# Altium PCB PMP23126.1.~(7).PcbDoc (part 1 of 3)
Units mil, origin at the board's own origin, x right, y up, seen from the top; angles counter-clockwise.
Board outline 1315.03 x 1390.8 mil, 6 copper layers (Top Layer, MidLayer1, MidLayer2, MidLayer3, MidLayer4, Bottom Layer), stack 72.6 mil thick; 49 components, 55 nets, 222 pads, 193 vias.
Unrouted connection lines stored in the file: 15.
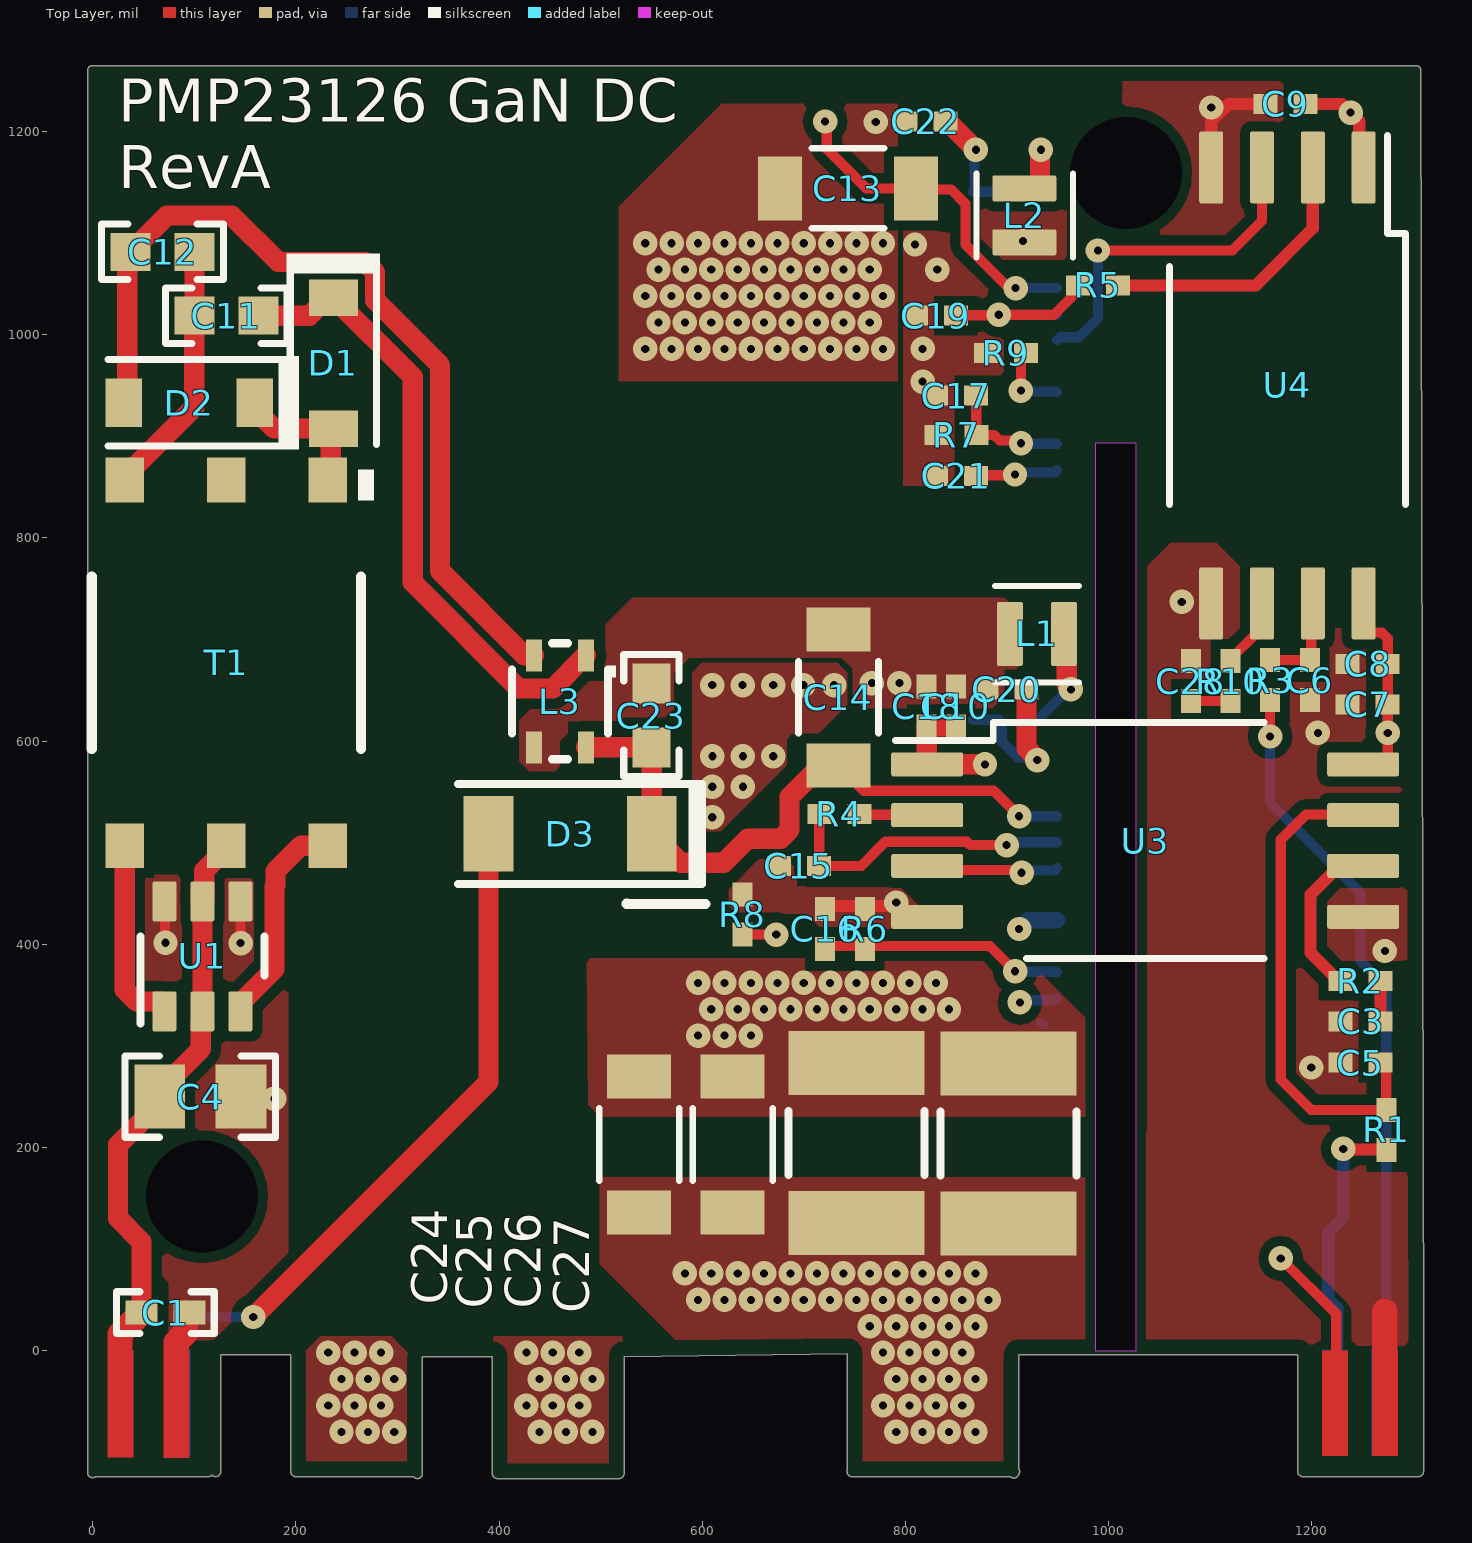
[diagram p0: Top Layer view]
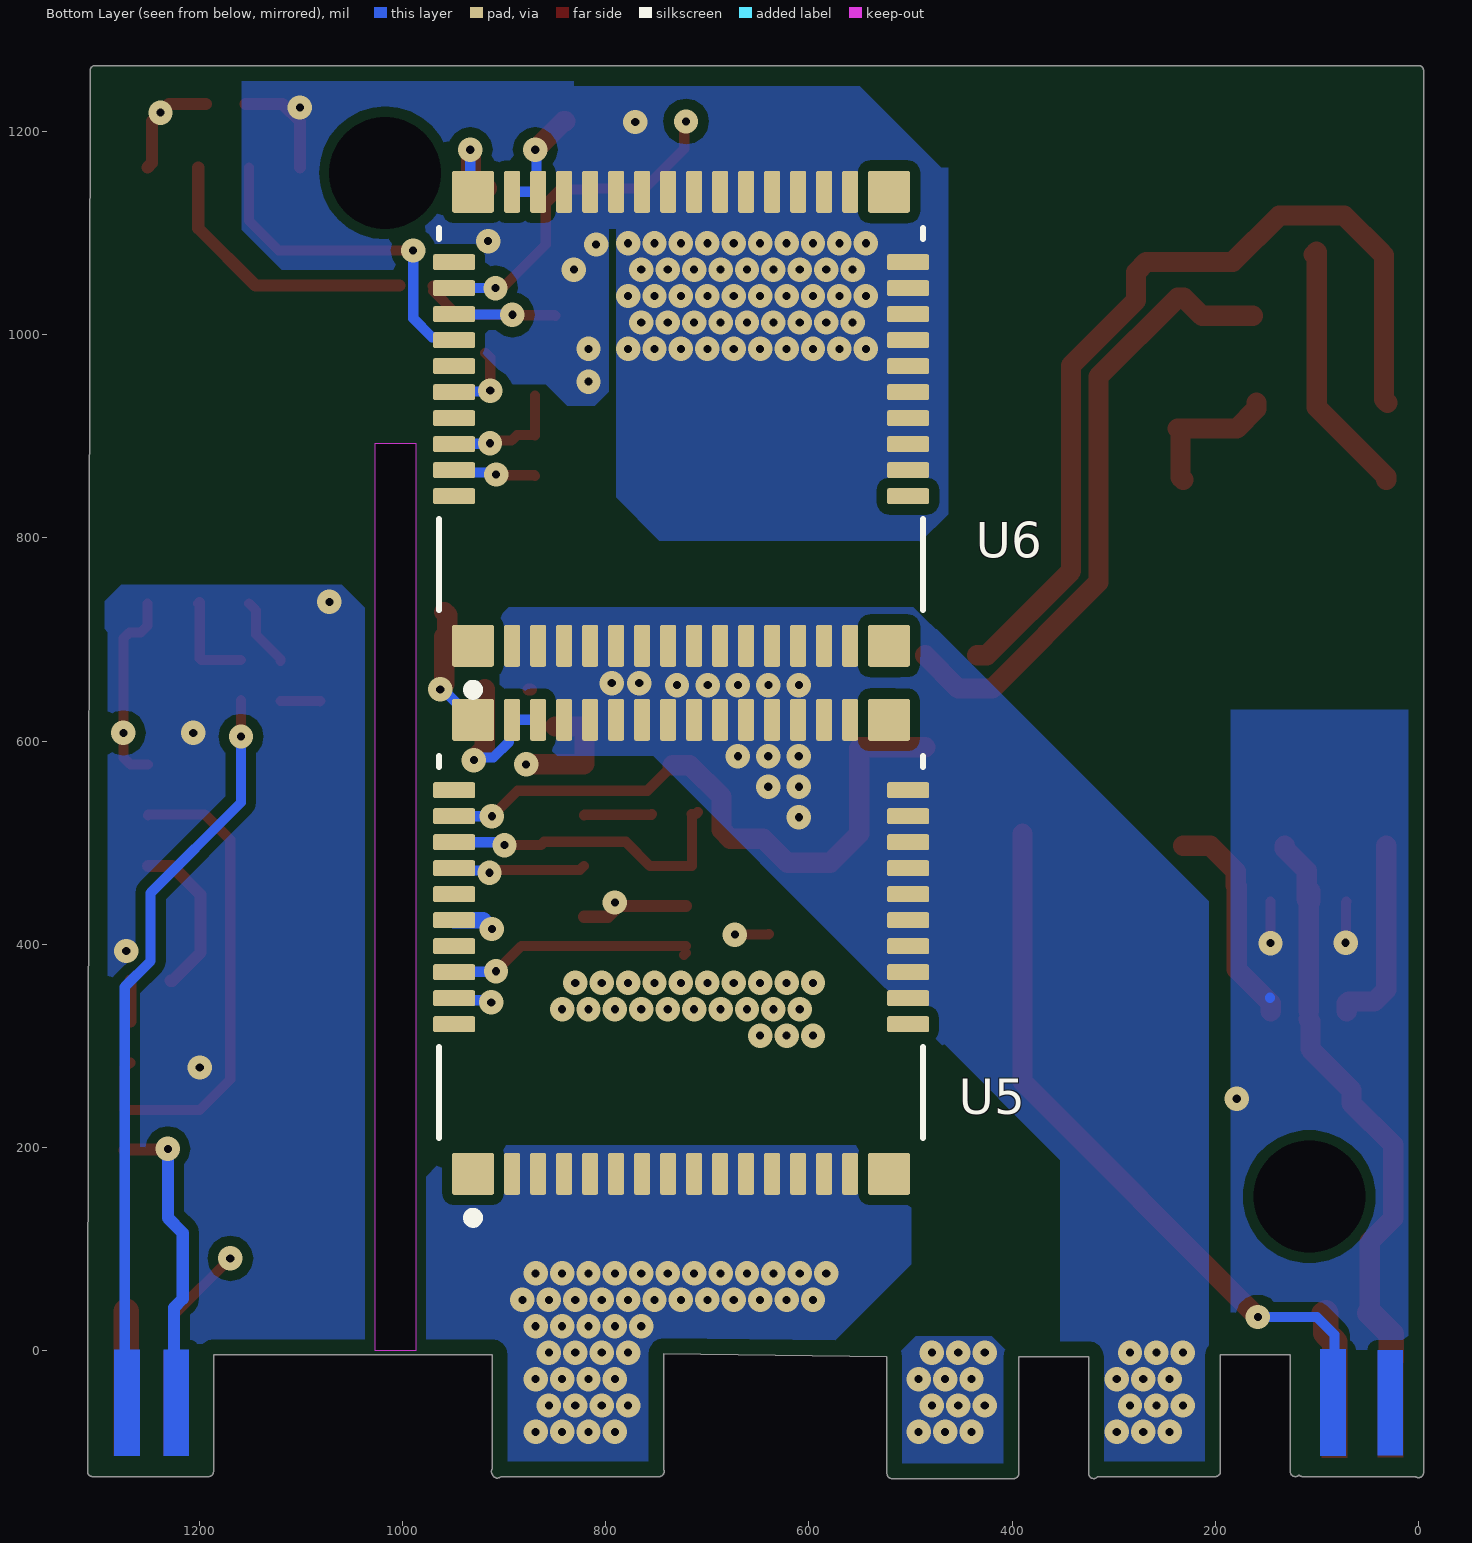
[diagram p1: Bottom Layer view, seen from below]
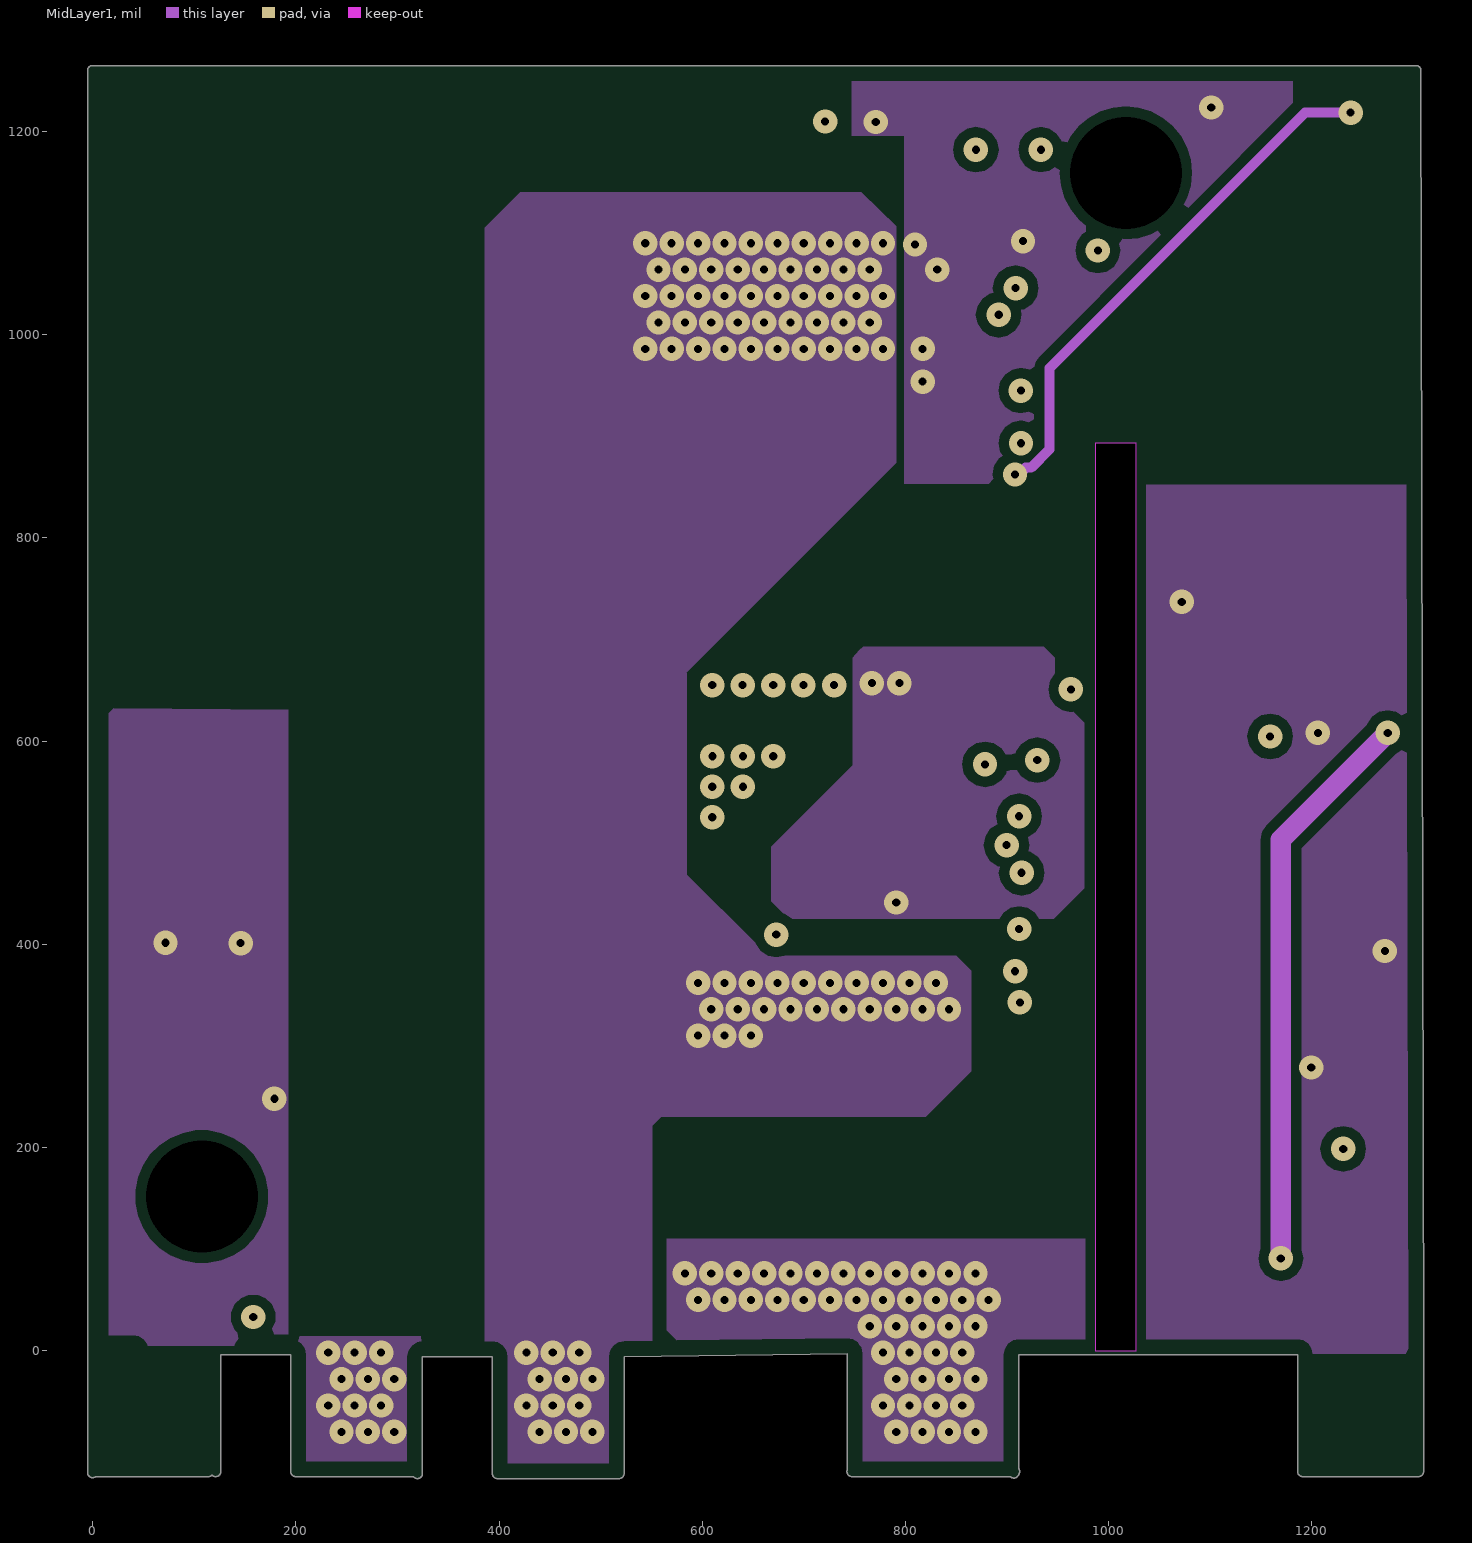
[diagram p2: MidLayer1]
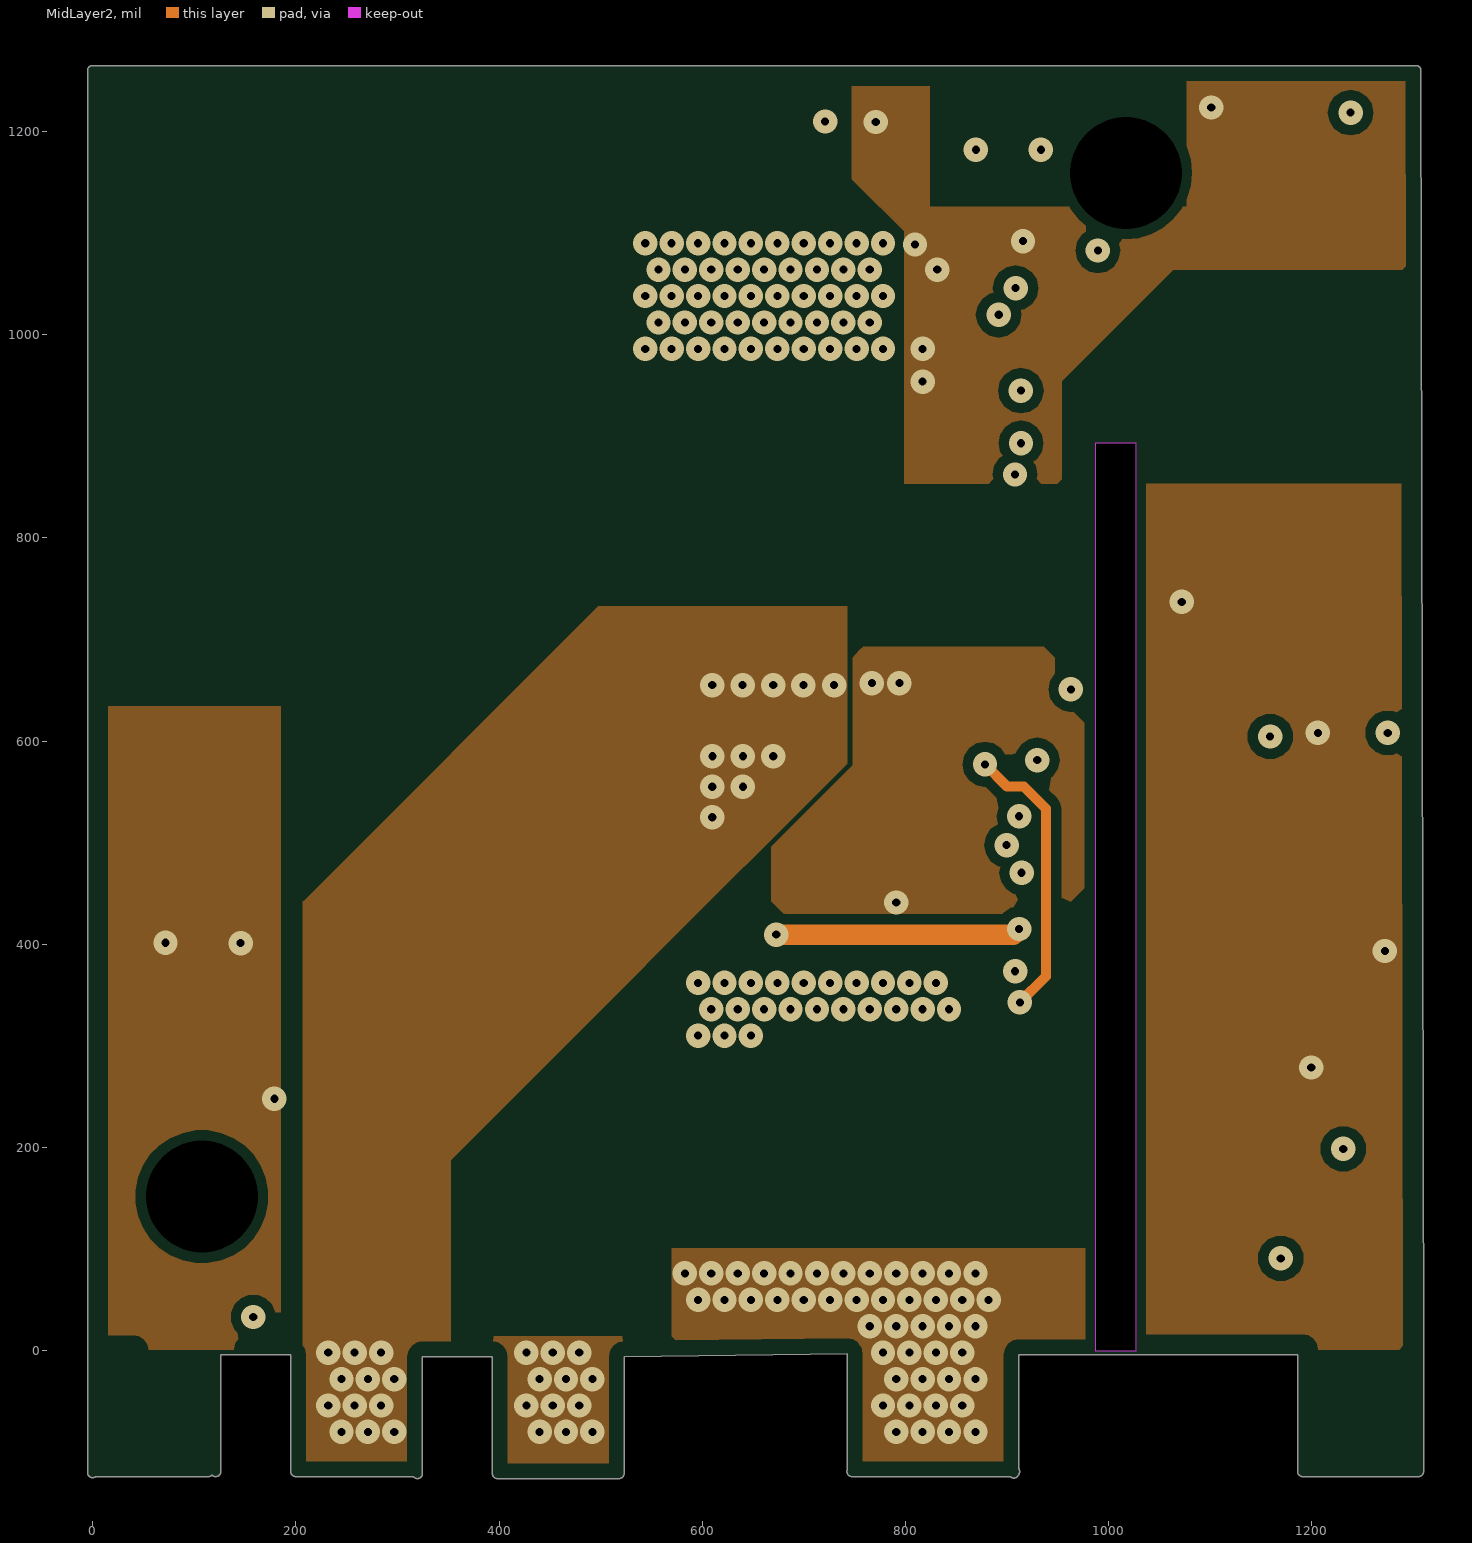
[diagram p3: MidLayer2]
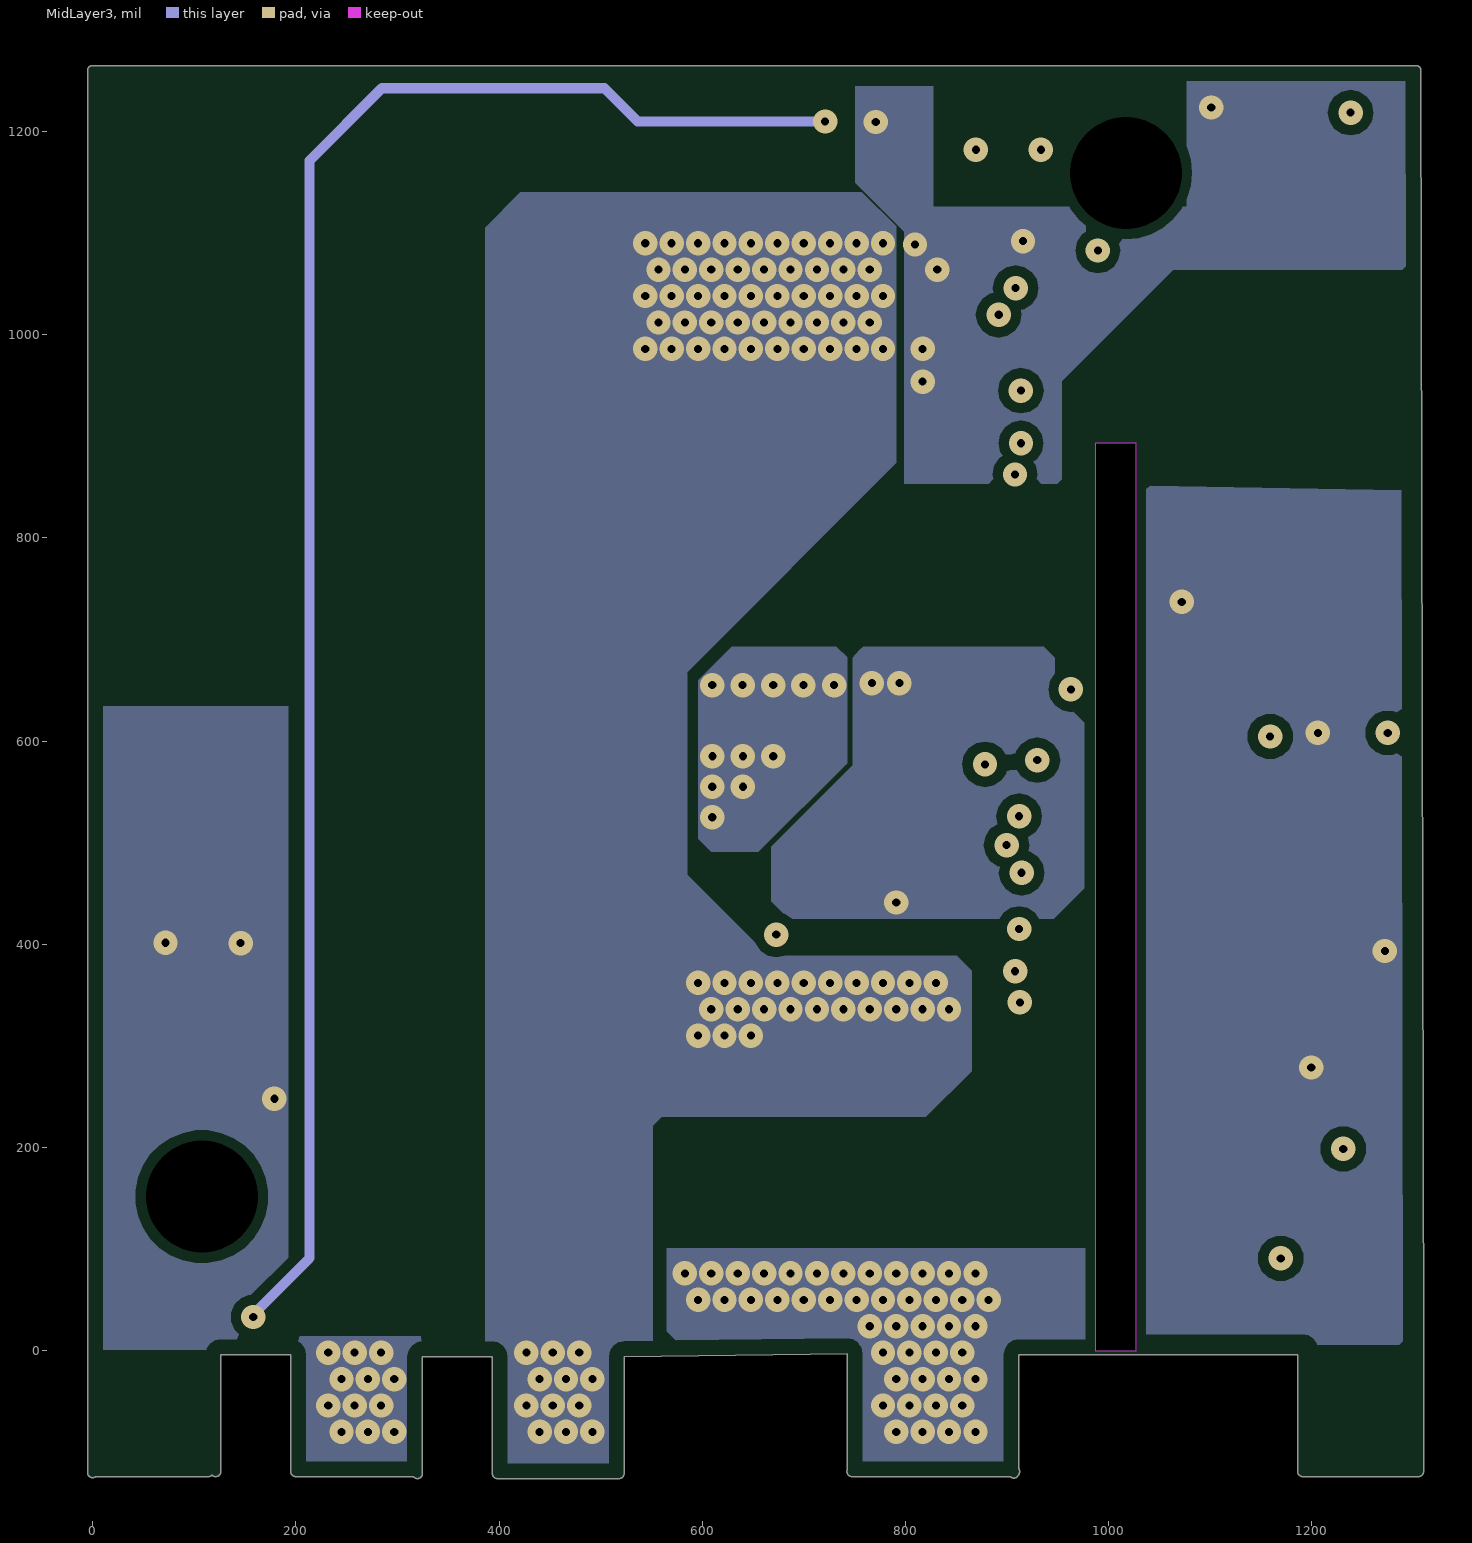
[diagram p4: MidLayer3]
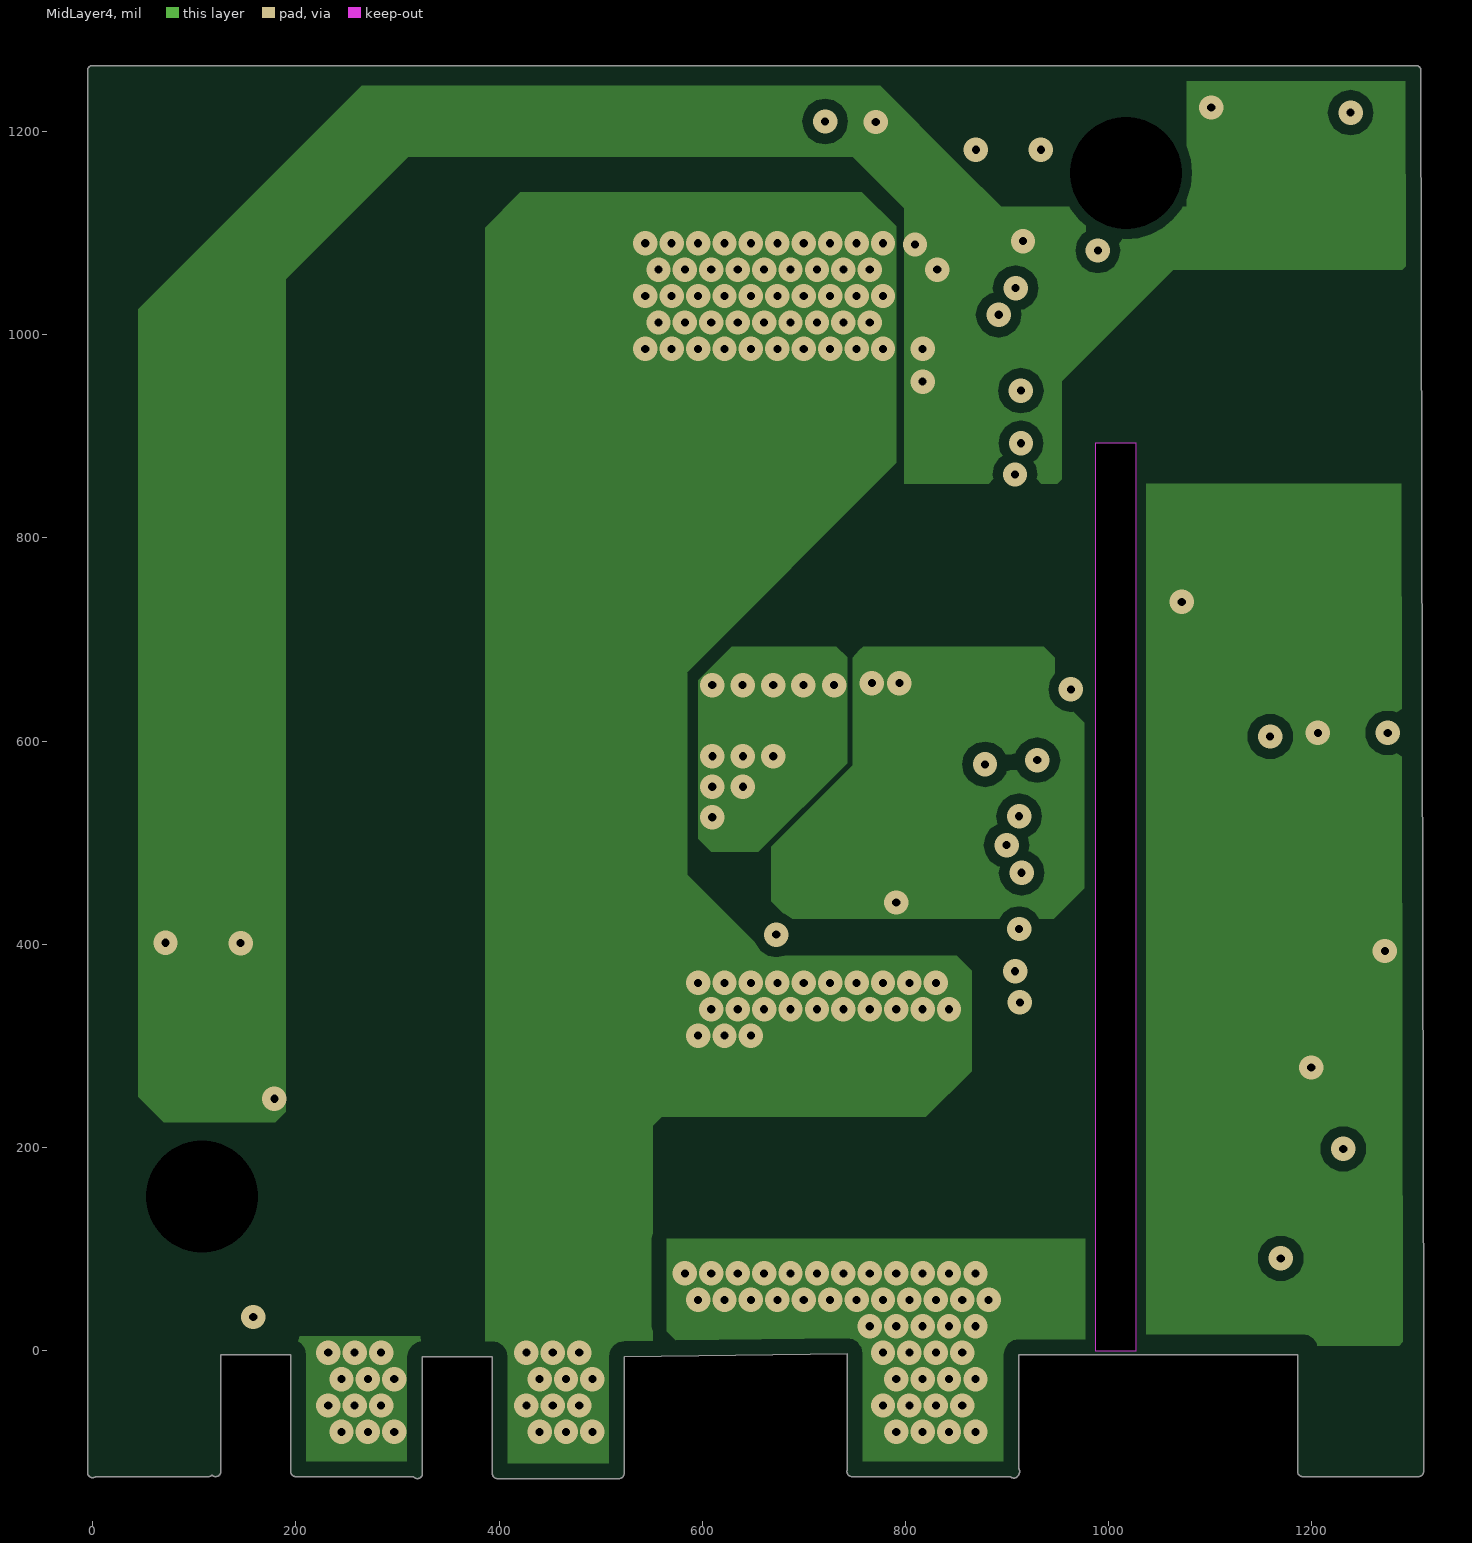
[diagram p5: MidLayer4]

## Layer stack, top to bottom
Top Solder: solder mask 0.4, Solder Resist, Dk 3.5
Top Layer: signal copper 2.8
Dielectric 1: prepreg 4.6, PP-016, Dk 4.4
MidLayer1: signal copper 2.8
Dielectric 2: core 21, Core-037, Dk 4.8
MidLayer2: signal copper 2.8
Dielectric 3: prepreg 4.6, PP-016, Dk 4.4
MidLayer3: signal copper 2.8
Dielectric 4: core 21, Core-037, Dk 4.8
MidLayer4: signal copper 2.8
Dielectric 5: prepreg 4.6, PP-016, Dk 4.4
Bottom Layer: signal copper 2.8
Bottom Solder: solder mask 0.4, Solder Resist, Dk 3.5

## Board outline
3,-124.01 114,-124.01 ccw(c114,-119) 117.6,-122.5 ccw(c121.19,-119) 126.21,-119 126.21,-4.01 194.92,-4.01 194.92,-119 ccw(c199.93,-119) 199.93,-124.01 315.72,-124.01 ccw(c319.67,-120.93) 324.69,-120.93 324.69,-5.95 393.4,-5.95 393.4,-120.93 ccw(c398.41,-120.93) 398.41,-125.95 518.15,-125.95 ccw(c518.15,-120.93) 523.17,-120.93 523.17,-5.88 742.79,-2.93 742.79,-117.12 ccw(c747.44,-119) 747.44,-124.01 903.2,-124.01 ccw(c906.71,-120.43) 911.49,-121.96 ccw(c907.44,-119) 912.46,-119 ccw(c907.44,-119) 911.73,-116.4 911.73,-4.01 1185.99,-4.01 1185.99,-119 ccw(c1191,-119) 1191,-124.01 1305,-124.01 ccw(c1305,-119) 1310.01,-119 1310.01,1 1307.46,1259.85 ccw(c1302.44,1259.84) 1302.44,1264.86 0,1264.86 ccw(c0,1259.84) -5.01,1259.84 -5.01,-120 ccw(c0,-120)
cut-out: 1027,0 1027,893 987,893 987,0

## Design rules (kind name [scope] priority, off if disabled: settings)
AcuteAngle [All] p1: minimum=4.50000000000000E+0001 checktracksonly=FALSE
AssemblyTestPointUsage [All] p1: valid=2
BoardOutlineClearance BoardOutlineClearance_MountingHoles [OnCopper and InComponentClass('Mounting Holes')] p1: gap=40 ignorepadtopadclearanceinfootprint=FALSE
BoardOutlineClearance BoardOutlineClearance_Poly [OnCopper and IsPoly] p2: gap=15 ignorepadtopadclearanceinfootprint=FALSE
BoardOutlineClearance [OnCopper and Not InComponentClass('Logo') and not InComponentClass('FiducialMark') and not InRegion(1000,500,4000,800) and not InPoly] p3: gap=8 ignorepadtopadclearanceinfootprint=FALSE
Clearance Clearance_3 [InNamedPolygon('BOTTOM_LAYER_54V1_P128')] p1: gap=10 ignorepadtopadclearanceinfootprint=TRUE except(0: Arc-Hole Track-Hole SMDPad-Hole THPad-Hole Via-Hole Fill-Hole Poly-Hole Region-Hole Text-Hole)
Clearance Clearance_2 [InNetClass('AC') vs Not InNetClass('AC')] p2: gap=50 ignorepadtopadclearanceinfootprint=TRUE
Clearance Clearance_1 [InNetClass('HV') vs Not InNetClass('HV')] p3: gap=40 ignorepadtopadclearanceinfootprint=TRUE
Clearance Clearance_Keepouts [((IsTrack Or IsArc) And Not InPoly) And IsFree and IsKeepOut vs ((IsTrack Or IsArc) And Not InPoly) And IsFree and IsKeepOut] p4: gap=0 ignorepadtopadclearanceinfootprint=TRUE
Clearance Clearance_Poly [InPolygon] p5: gap=10 ignorepadtopadclearanceinfootprint=TRUE
Clearance Clearance_FiducialMark [IsKeepOut and InComponentClass('FiducialMark') vs IsPad and InComponentClass('FiducialMark')] p6: gap=0 ignorepadtopadclearanceinfootprint=FALSE
Clearance [All] p7: gap=7 ignorepadtopadclearanceinfootprint=FALSE
ComponentClearance ComponentClearance_MountingHoles_FiducialMarks [InComponentClass('Mounting Holes') vs InComponentClass('FiducialMark')] p1: gap=50 collisioncheckmode=3 verticalgap=10 showdistances=FALSE
ComponentClearance ComponentClearance_Shunt [InComponentClass('Header') vs InComponentClass('Shunt')] p2: gap=0 collisioncheckmode=3 verticalgap=0 showdistances=FALSE
ComponentClearance ComponentClearance_Logo [InComponentClass('Logo')] p3: gap=10 collisioncheckmode=3 verticalgap=10 showdistances=FALSE
ComponentClearance ComponentClearance_ScrewToNut [(HasFootprint('NY PMS 440 0025 PH')) vs (HasFootprint('Keystone_1902C'))] p4: gap=5 collisioncheckmode=3 verticalgap=10 showdistances=FALSE
ComponentClearance ComponentClearance_MountingHoles [InComponentClass('Mounting Holes')] p5: gap=50 collisioncheckmode=3 verticalgap=100000 showdistances=FALSE
ComponentClearance ComponentClearance_SmallPassives [HasFootprint('0201*') or HasFootprint('0402*') or HasFootprint('0508') or HasFootprint('0603*') or HasFootprint('0612') or HasFootprint('0805*') or HasFootprint('0815*') or HasFootprint('0830*') or HasFootprint('1206*') or HasFootprint('1210*') or HasFootprint('1808*') or HasFootprint('1812*') or HasFootprint('1825*') or HasFootprint('2010*') or HasFootprint('2220*') or HasFootprint('2225*') or HasFootprint('2512*') or HasFootprint('2728*') or HasFootprint('3518*') vs HasFootprint('0201*') or HasFootprint('0402*') or HasFootprint('0508') or HasFootprint('0603*') or HasFootprint('0612') or HasFootprint('0805*') or HasFootprint('0815*') or HasFootprint('0830*') or HasFootprint('1206*') or HasFootprint('1210*') or HasFootprint('1808*') or HasFootprint('1812*') or HasFootprint('1825*') or HasFootprint('2010*') or HasFootprint('2220*') or HasFootprint('2225*') or HasFootprint('2512*') or HasFootprint('2728*') or HasFootprint('3518*')] p6: gap=14.96 collisioncheckmode=3 verticalgap=10 showdistances=FALSE
ComponentClearance ComponentClearance_THtoSMT [IsThruComponent vs IsSMTComponent] p7: gap=10 collisioncheckmode=3 verticalgap=10 showdistances=FALSE
ComponentClearance ComponentClearance_THtoTH [IsThruComponent vs IsThruComponent] p8: gap=10 collisioncheckmode=3 verticalgap=10 showdistances=FALSE
ComponentClearance [All] p9: gap=10 collisioncheckmode=3 verticalgap=10 showdistances=FALSE
DiffPairsRouting [All] p1: maxlimit=100 minlimit=10 mostfreqgap=10 substack1={A02F224D-4808-492E-A71F-5F5656FBF0D4} toplayer_{a02f224d-4808-492e-a71f-5f5656fbf0d4}_minwidth=15 toplayer_{a02f224d-4808-492e-a71f-5f5656fbf0d4}_maxwidth=15 toplayer_{a02f224d-4808-492e-a71f-5f5656fbf0d4}_prefwidth=15 midlayer1_{a02f224d-4808-492e-a71f-5f5656fbf0d4}_minwidth=15 midlayer1_{a02f224d-4808-492e-a71f-5f5656fbf0d4}_maxwidth=15 midlayer1_{a02f224d-4808-492e-a71f-5f5656fbf0d4}_prefwidth=15 midlayer2_{a02f224d-4808-492e-a71f-5f5656fbf0d4}_minwidth=15 midlayer2_{a02f224d-4808-492e-a71f-5f5656fbf0d4}_maxwidth=15 midlayer2_{a02f224d-4808-492e-a71f-5f5656fbf0d4}_prefwidth=15 midlayer3_{a02f224d-4808-492e-a71f-5f5656fbf0d4}_minwidth=15 midlayer3_{a02f224d-4808-492e-a71f-5f5656fbf0d4}_maxwidth=15 midlayer3_{a02f224d-4808-492e-a71f-5f5656fbf0d4}_prefwidth=15 midlayer4_{a02f224d-4808-492e-a71f-5f5656fbf0d4}_minwidth=15 midlayer4_{a02f224d-4808-492e-a71f-5f5656fbf0d4}_maxwidth=15 midlayer4_{a02f224d-4808-492e-a71f-5f5656fbf0d4}_prefwidth=15 bottomlayer_{a02f224d-4808-492e-a71f-5f5656fbf0d4}_minwidth=15 bottomlayer_{a02f224d-4808-492e-a71f-5f5656fbf0d4}_maxwidth=15 bottomlayer_{a02f224d-4808-492e-a71f-5f5656fbf0d4}_prefwidth=15 substack2={B838D286-A00B-4EE2-88E1-F79279CC64B4} toplayer_{b838d286-a00b-4ee2-88e1-f79279cc64b4}_minwidth=15 toplayer_{b838d286-a00b-4ee2-88e1-f79279cc64b4}_maxwidth=15 toplayer_{b838d286-a00b-4ee2-88e1-f79279cc64b4}_prefwidth=15 midlayer1_{b838d286-a00b-4ee2-88e1-f79279cc64b4}_minwidth=15 midlayer1_{b838d286-a00b-4ee2-88e1-f79279cc64b4}_maxwidth=15 midlayer1_{b838d286-a00b-4ee2-88e1-f79279cc64b4}_prefwidth=15 midlayer2_{b838d286-a00b-4ee2-88e1-f79279cc64b4}_minwidth=15 midlayer2_{b838d286-a00b-4ee2-88e1-f79279cc64b4}_maxwidth=15 midlayer2_{b838d286-a00b-4ee2-88e1-f79279cc64b4}_prefwidth=15 midlayer3_{b838d286-a00b-4ee2-88e1-f79279cc64b4}_minwidth=15 midlayer3_{b838d286-a00b-4ee2-88e1-f79279cc64b4}_maxwidth=15 midlayer3_{b838d286-a00b-4ee2-88e1-f79279cc64b4}_prefwidth=15 midlayer4_{b838d286-a00b-4ee2-88e1-f79279cc64b4}_minwidth=15 midlayer4_{b838d286-a00b-4ee2-88e1-f79279cc64b4}_maxwidth=15 midlayer4_{b838d286-a00b-4ee2-88e1-f79279cc64b4}_prefwidth=15 bottomlayer_{b838d286-a00b-4ee2-88e1-f79279cc64b4}_minwidth=15 bottomlayer_{b838d286-a00b-4ee2-88e1-f79279cc64b4}_maxwidth=15 bottomlayer_{b838d286-a00b-4ee2-88e1-f79279cc64b4}_prefwidth=15 substack3={0D253197-D122-4D2B-9584-B8C12AA3806F} toplayer_{0d253197-d122-4d2b-9584-b8c12aa3806f}_minwidth=15 toplayer_{0d253197-d122-4d2b-9584-b8c12aa3806f}_maxwidth=15 toplayer_{0d253197-d122-4d2b-9584-b8c12aa3806f}_prefwidth=15 midlayer1_{0d253197-d122-4d2b-9584-b8c12aa3806f}_minwidth=15 midlayer1_{0d253197-d122-4d2b-9584-b8c12aa3806f}_maxwidth=15 midlayer1_{0d253197-d122-4d2b-9584-b8c12aa3806f}_prefwidth=15 midlayer2_{0d253197-d122-4d2b-9584-b8c12aa3806f}_minwidth=15 midlayer2_{0d253197-d122-4d2b-9584-b8c12aa3806f}_maxwidth=15 midlayer2_{0d253197-d122-4d2b-9584-b8c12aa3806f}_prefwidth=15 midlayer3_{0d253197-d122-4d2b-9584-b8c12aa3806f}_minwidth=15 midlayer3_{0d253197-d122-4d2b-9584-b8c12aa3806f}_maxwidth=15 midlayer3_{0d253197-d122-4d2b-9584-b8c12aa3806f}_prefwidth=15 midlayer4_{0d253197-d122-4d2b-9584-b8c12aa3806f}_minwidth=15 midlayer4_{0d253197-d122-4d2b-9584-b8c12aa3806f}_maxwidth=15 midlayer4_{0d253197-d122-4d2b-9584-b8c12aa3806f}_prefwidth=15 bottomlayer_{0d253197-d122-4d2b-9584-b8c12aa3806f}_minwidth=15 bottomlayer_{0d253197-d122-4d2b-9584-b8c12aa3806f}_maxwidth=15 bottomlayer_{0d253197-d122-4d2b-9584-b8c12aa3806f}_prefwidth=15 substack4={88BCB183-C685-456E-B90A-365A53404C2C} toplayer_{88bcb183-c685-456e-b90a-365a53404c2c}_minwidth=15 toplayer_{88bcb183-c685-456e-b90a-365a53404c2c}_maxwidth=15 toplayer_{88bcb183-c685-456e-b90a-365a53404c2c}_prefwidth=15 midlayer1_{88bcb183-c685-456e-b90a-365a53404c2c}_minwidth=15 midlayer1_{88bcb183-c685-456e-b90a-365a53404c2c}_maxwidth=15 midlayer1_{88bcb183-c685-456e-b90a-365a53404c2c}_prefwidth=15 midlayer2_{88bcb183-c685-456e-b90a-365a53404c2c}_minwidth=15 midlayer2_{88bcb183-c685-456e-b90a-365a53404c2c}_maxwidth=15 midlayer2_{88bcb183-c685-456e-b90a-365a53404c2c}_prefwidth=15 midlayer3_{88bcb183-c685-456e-b90a-365a53404c2c}_minwidth=15 midlayer3_{88bcb183-c685-456e-b90a-365a53404c2c}_maxwidth=15 midlayer3_{88bcb183-c685-456e-b90a-365a53404c2c}_prefwidth=15 midlayer4_{88bcb183-c685-456e-b90a-365a53404c2c}_minwidth=15 midlayer4_{88bcb183-c685-456e-b90a-365a53404c2c}_maxwidth=15 midlayer4_{88bcb183-c685-456e-b90a-365a53404c2c}_prefwidth=15 bottomlayer_{88bcb183-c685-456e-b90a-365a53404c2c}_minwidth=15 bottomlayer_{88bcb183-c685-456e-b90a-365a53404c2c}_maxwidth=15 bottomlayer_{88bcb183-c685-456e-b90a-365a53404c2c}_prefwidth=15 substack5={4C8C2325-90D5-40B8-8B6B-4F66D44EFE25} toplayer_{4c8c2325-90d5-40b8-8b6b-4f66d44efe25}_minwidth=15 toplayer_{4c8c2325-90d5-40b8-8b6b-4f66d44efe25}_maxwidth=15 toplayer_{4c8c2325-90d5-40b8-8b6b-4f66d44efe25}_prefwidth=15 midlayer1_{4c8c2325-90d5-40b8-8b6b-4f66d44efe25}_minwidth=15 midlayer1_{4c8c2325-90d5-40b8-8b6b-4f66d44efe25}_maxwidth=15 midlayer1_{4c8c2325-90d5-40b8-8b6b-4f66d44efe25}_prefwidth=15 midlayer2_{4c8c2325-90d5-40b8-8b6b-4f66d44efe25}_minwidth=15 midlayer2_{4c8c2325-90d5-40b8-8b6b-4f66d44efe25}_maxwidth=15 midlayer2_{4c8c2325-90d5-40b8-8b6b-4f66d44efe25}_prefwidth=15 midlayer3_{4c8c2325-90d5-40b8-8b6b-4f66d44efe25}_minwidth=15 midlayer3_{4c8c2325-90d5-40b8-8b6b-4f66d44efe25}_maxwidth=15 midlayer3_{4c8c2325-90d5-40b8-8b6b-4f66d44efe25}_prefwidth=15 midlayer4_{4c8c2325-90d5-40b8-8b6b-4f66d44efe25}_minwidth=15 midlayer4_{4c8c2325-90d5-40b8-8b6b-4f66d44efe25}_maxwidth=15 midlayer4_{4c8c2325-90d5-40b8-8b6b-4f66d44efe25}_prefwidth=15 bottomlayer_{4c8c2325-90d5-40b8-8b6b-4f66d44efe25}_minwidth=15 bottomlayer_{4c8c2325-90d5-40b8-8b6b-4f66d44efe25}_maxwidth=15 bottomlayer_{4c8c2325-90d5-40b8-8b6b-4f66d44efe25}_prefwidth=15 toplayer_minwidth=15 toplayer_maxwidth=15 toplayer_prefwidth=15 midlayer1_minwidth=15 midlayer1_maxwidth=15 midlayer1_prefwidth=15 midlayer2_minwidth=15 midlayer2_maxwidth=15 midlayer2_prefwidth=15 midlayer3_minwidth=15 midlayer3_maxwidth=15 midlayer3_prefwidth=15 midlayer4_minwidth=15 midlayer4_maxwidth=15 midlayer4_prefwidth=15 bottomlayer_minwidth=15 bottomlayer_maxwidth=15 bottomlayer_prefwidth=15 substack6={553D66F5-99EF-40B1-BA7C-73E3B04B176F} toplayer_{553d66f5-99ef-40b1-ba7c-73e3b04b176f}_minwidth=15 toplayer_{553d66f5-99ef-40b1-ba7c-73e3b04b176f}_maxwidth=15 toplayer_{553d66f5-99ef-40b1-ba7c-73e3b04b176f}_prefwidth=15 midlayer1_{553d66f5-99ef-40b1-ba7c-73e3b04b176f}_minwidth=15 midlayer1_{553d66f5-99ef-40b1-ba7c-73e3b04b176f}_maxwidth=15 midlayer1_{553d66f5-99ef-40b1-ba7c-73e3b04b176f}_prefwidth=15 midlayer2_{553d66f5-99ef-40b1-ba7c-73e3b04b176f}_minwidth=15 midlayer2_{553d66f5-99ef-40b1-ba7c-73e3b04b176f}_maxwidth=15 midlayer2_{553d66f5-99ef-40b1-ba7c-73e3b04b176f}_prefwidth=15 midlayer3_{553d66f5-99ef-40b1-ba7c-73e3b04b176f}_minwidth=15 midlayer3_{553d66f5-99ef-40b1-ba7c-73e3b04b176f}_maxwidth=15 midlayer3_{553d66f5-99ef-40b1-ba7c-73e3b04b176f}_prefwidth=15 midlayer4_{553d66f5-99ef-40b1-ba7c-73e3b04b176f}_minwidth=15 midlayer4_{553d66f5-99ef-40b1-ba7c-73e3b04b176f}_maxwidth=15 midlayer4_{553d66f5-99ef-40b1-ba7c-73e3b04b176f}_prefwidth=15 bottomlayer_{553d66f5-99ef-40b1-ba7c-73e3b04b176f}_minwidth=15 bottomlayer_{553d66f5-99ef-40b1-ba7c-73e3b04b176f}_maxwidth=15 bottomlayer_{553d66f5-99ef-40b1-ba7c-73e3b04b176f}_prefwidth=15 substack7={FF0C9878-5A48-402E-B013-8E2EEFCEDCCB} toplayer_{ff0c9878-5a48-402e-b013-8e2eefcedccb}_minwidth=15 toplayer_{ff0c9878-5a48-402e-b013-8e2eefcedccb}_maxwidth=15 toplayer_{ff0c9878-5a48-402e-b013-8e2eefcedccb}_prefwidth=15 midlayer1_{ff0c9878-5a48-402e-b013-8e2eefcedccb}_minwidth=15 midlayer1_{ff0c9878-5a48-402e-b013-8e2eefcedccb}_maxwidth=15 midlayer1_{ff0c9878-5a48-402e-b013-8e2eefcedccb}_prefwidth=15 midlayer2_{ff0c9878-5a48-402e-b013-8e2eefcedccb}_minwidth=15 midlayer2_{ff0c9878-5a48-402e-b013-8e2eefcedccb}_maxwidth=15 midlayer2_{ff0c9878-5a48-402e-b013-8e2eefcedccb}_prefwidth=15 midlayer3_{ff0c9878-5a48-402e-b013-8e2eefcedccb}_minwidth=15 midlayer3_{ff0c9878-5a48-402e-b013-8e2eefcedccb}_maxwidth=15 midlayer3_{ff0c9878-5a48-402e-b013-8e2eefcedccb}_prefwidth=15 midlayer4_{ff0c9878-5a48-402e-b013-8e2eefcedccb}_minwidth=15 midlayer4_{ff0c9878-5a48-402e-b013-8e2eefcedccb}_maxwidth=15 midlayer4_{ff0c9878-5a48-402e-b013-8e2eefcedccb}_prefwidth=15 bottomlayer_{ff0c9878-5a48-402e-b013-8e2eefcedccb}_minwidth=15 bottomlayer_{ff0c9878-5a48-402e-b013-8e2eefcedccb}_maxwidth=15 bottomlayer_{ff0c9878-5a48-402e-b013-8e2eefcedccb}_prefwidth=15 substack8={5BB5B65B-6C7F-4868-A6AE-66DD57ADDCBD} toplayer_{5bb5b65b-6c7f-4868-a6ae-66dd57addcbd}_minwidth=15 toplayer_{5bb5b65b-6c7f-4868-a6ae-66dd57addcbd}_maxwidth=15 toplayer_{5bb5b65b-6c7f-4868-a6ae-66dd57addcbd}_prefwidth=15 midlayer1_{5bb5b65b-6c7f-4868-a6ae-66dd57addcbd}_minwidth=15 midlayer1_{5bb5b65b-6c7f-4868-a6ae-66dd57addcbd}_maxwidth=15 midlayer1_{5bb5b65b-6c7f-4868-a6ae-66dd57addcbd}_prefwidth=15 midlayer2_{5bb5b65b-6c7f-4868-a6ae-66dd57addcbd}_minwidth=15 midlayer2_{5bb5b65b-6c7f-4868-a6ae-66dd57addcbd}_maxwidth=15 midlayer2_{5bb5b65b-6c7f-4868-a6ae-66dd57addcbd}_prefwidth=15 midlayer3_{5bb5b65b-6c7f-4868-a6ae-66dd57addcbd}_minwidth=15 midlayer3_{5bb5b65b-6c7f-4868-a6ae-66dd57addcbd}_maxwidth=15 midlayer3_{5bb5b65b-6c7f-4868-a6ae-66dd57addcbd}_prefwidth=15 midlayer4_{5bb5b65b-6c7f-4868-a6ae-66dd57addcbd}_minwidth=15 midlayer4_{5bb5b65b-6c7f-4868-a6ae-66dd57addcbd}_maxwidth=15 midlayer4_{5bb5b65b-6c7f-4868-a6ae-66dd57addcbd}_prefwidth=15 bottomlayer_{5bb5b65b-6c7f-4868-a6ae-66dd57addcbd}_minwidth=15 bottomlayer_{5bb5b65b-6c7f-4868-a6ae-66dd57addcbd}_maxwidth=15 bottomlayer_{5bb5b65b-6c7f-4868-a6ae-66dd57addcbd}_prefwidth=15 substack9={65866CD6-1929-42AF-BAA8-019D5E6BA212} toplayer_{65866cd6-1929-42af-baa8-019d5e6ba212}_minwidth=15 toplayer_{65866cd6-1929-42af-baa8-019d5e6ba212}_maxwidth=15 toplayer_{65866cd6-1929-42af-baa8-019d5e6ba212}_prefwidth=15 midlayer1_{65866cd6-1929-42af-baa8-019d5e6ba212}_minwidth=15 midlayer1_{65866cd6-1929-42af-baa8-019d5e6ba212}_maxwidth=15 midlayer1_{65866cd6-1929-42af-baa8-019d5e6ba212}_prefwidth=15 midlayer2_{65866cd6-1929-42af-baa8-019d5e6ba212}_minwidth=15 midlayer2_{65866cd6-1929-42af-baa8-019d5e6ba212}_maxwidth=15 midlayer2_{65866cd6-1929-42af-baa8-019d5e6ba212}_prefwidth=15 midlayer3_{65866cd6-1929-42af-baa8-019d5e6ba212}_minwidth=15 midlayer3_{65866cd6-1929-42af-baa8-019d5e6ba212}_maxwidth=15 midlayer3_{65866cd6-1929-42af-baa8-019d5e6ba212}_prefwidth=15 midlayer4_{65866cd6-1929-42af-baa8-019d5e6ba212}_minwidth=15 midlayer4_{65866cd6-1929-42af-baa8-019d5e6ba212}_maxwidth=15 midlayer4_{65866cd6-1929-42af-baa8-019d5e6ba212}_prefwidth=15 bottomlayer_{65866cd6-1929-42af-baa8-019d5e6ba212}_minwidth=15 bottomlayer_{65866cd6-1929-42af-baa8-019d5e6ba212}_maxwidth=15 bottomlayer_{65866cd6-1929-42af-baa8-019d5e6ba212}_prefwidth=15 substack10={590F0BEA-1E04-4904-B9C9-D9D160075BC2} toplayer_{590f0bea-1e04-4904-b9c9-d9d160075bc2}_minwidth=15 toplayer_{590f0bea-1e04-4904-b9c9-d9d160075bc2}_maxwidth=15 toplayer_{590f0bea-1e04-4904-b9c9-d9d160075bc2}_prefwidth=15 midlayer1_{590f0bea-1e04-4904-b9c9-d9d160075bc2}_minwidth=15 midlayer1_{590f0bea-1e04-4904-b9c9-d9d160075bc2}_maxwidth=15 midlayer1_{590f0bea-1e04-4904-b9c9-d9d160075bc2}_prefwidth=15 midlayer2_{590f0bea-1e04-4904-b9c9-d9d160075bc2}_minwidth=15 midlayer2_{590f0bea-1e04-4904-b9c9-d9d160075bc2}_maxwidth=15 midlayer2_{590f0bea-1e04-4904-b9c9-d9d160075bc2}_prefwidth=15 midlayer3_{590f0bea-1e04-4904-b9c9-d9d160075bc2}_minwidth=15 midlayer3_{590f0bea-1e04-4904-b9c9-d9d160075bc2}_maxwidth=15 midlayer3_{590f0bea-1e04-4904-b9c9-d9d160075bc2}_prefwidth=15 midlayer4_{590f0bea-1e04-4904-b9c9-d9d160075bc2}_minwidth=15 midlayer4_{590f0bea-1e04-4904-b9c9-d9d160075bc2}_maxwidth=15 midlayer4_{590f0bea-1e04-4904-b9c9-d9d160075bc2}_prefwidth=15 bottomlayer_{590f0bea-1e04-4904-b9c9-d9d160075bc2}_minwidth=15 bottomlayer_{590f0bea-1e04-4904-b9c9-d9d160075bc2}_maxwidth=15 bottomlayer_{590f0bea-1e04-4904-b9c9-d9d160075bc2}_prefwidth=15 substack11={B2AC4F48-1A5F-44D7-A91B-3BAADFDAAED0} toplayer_{b2ac4f48-1a5f-44d7-a91b-3baadfdaaed0}_minwidth=15 toplayer_{b2ac4f48-1a5f-44d7-a91b-3baadfdaaed0}_maxwidth=15 toplayer_{b2ac4f48-1a5f-44d7-a91b-3baadfdaaed0}_prefwidth=15 midlayer1_{b2ac4f48-1a5f-44d7-a91b-3baadfdaaed0}_minwidth=15 midlayer1_{b2ac4f48-1a5f-44d7-a91b-3baadfdaaed0}_maxwidth=15 midlayer1_{b2ac4f48-1a5f-44d7-a91b-3baadfdaaed0}_prefwidth=15 midlayer2_{b2ac4f48-1a5f-44d7-a91b-3baadfdaaed0}_minwidth=15 midlayer2_{b2ac4f48-1a5f-44d7-a91b-3baadfdaaed0}_maxwidth=15 midlayer2_{b2ac4f48-1a5f-44d7-a91b-3baadfdaaed0}_prefwidth=15 midlayer3_{b2ac4f48-1a5f-44d7-a91b-3baadfdaaed0}_minwidth=15 midlayer3_{b2ac4f48-1a5f-44d7-a91b-3baadfdaaed0}_maxwidth=15 midlayer3_{b2ac4f48-1a5f-44d7-a91b-3baadfdaaed0}_prefwidth=15 midlayer4_{b2ac4f48-1a5f-44d7-a91b-3baadfdaaed0}_minwidth=15 midlayer4_{b2ac4f48-1a5f-44d7-a91b-3baadfdaaed0}_maxwidth=15 midlayer4_{b2ac4f48-1a5f-44d7-a91b-3baadfdaaed0}_prefwidth=15 bottomlayer_{b2ac4f48-1a5f-44d7-a91b-3baadfdaaed0}_minwidth=15 bottomlayer_{b2ac4f48-1a5f-44d7-a91b-3baadfdaaed0}_maxwidth=15 bottomlayer_{b2ac4f48-1a5f-44d7-a91b-3baadfdaaed0}_prefwidth=15 substack12={DD3D4156-A54D-4E1F-B7FF-E5EF72C45496} toplayer_{dd3d4156-a54d-4e1f-b7ff-e5ef72c45496}_minwidth=15 toplayer_{dd3d4156-a54d-4e1f-b7ff-e5ef72c45496}_maxwidth=15 toplayer_{dd3d4156-a54d-4e1f-b7ff-e5ef72c45496}_prefwidth=15 midlayer1_{dd3d4156-a54d-4e1f-b7ff-e5ef72c45496}_minwidth=15 midlayer1_{dd3d4156-a54d-4e1f-b7ff-e5ef72c45496}_maxwidth=15 midlayer1_{dd3d4156-a54d-4e1f-b7ff-e5ef72c45496}_prefwidth=15 midlayer2_{dd3d4156-a54d-4e1f-b7ff-e5ef72c45496}_minwidth=15 midlayer2_{dd3d4156-a54d-4e1f-b7ff-e5ef72c45496}_maxwidth=15 midlayer2_{dd3d4156-a54d-4e1f-b7ff-e5ef72c45496}_prefwidth=15 midlayer3_{dd3d4156-a54d-4e1f-b7ff-e5ef72c45496}_minwidth=15 midlayer3_{dd3d4156-a54d-4e1f-b7ff-e5ef72c45496}_maxwidth=15 midlayer3_{dd3d4156-a54d-4e1f-b7ff-e5ef72c45496}_prefwidth=15 midlayer4_{dd3d4156-a54d-4e1f-b7ff-e5ef72c45496}_minwidth=15 midlayer4_{dd3d4156-a54d-4e1f-b7ff-e5ef72c45496}_maxwidth=15 midlayer4_{dd3d4156-a54d-4e1f-b7ff-e5ef72c45496}_prefwidth=15 bottomlayer_{dd3d4156-a54d-4e1f-b7ff-e5ef72c45496}_minwidth=15 bottomlayer_{dd3d4156-a54d-4e1f-b7ff-e5ef72c45496}_maxwidth=15 bottomlayer_{dd3d4156-a54d-4e1f-b7ff-e5ef72c45496}_prefwidth=15 substack13={7CC4AE65-1EB7-43C1-8FCA-3677EE54F737} toplayer_{7cc4ae65-1eb7-43c1-8fca-3677ee54f737}_minwidth=15 toplayer_{7cc4ae65-1eb7-43c1-8fca-3677ee54f737}_maxwidth=15 toplayer_{7cc4ae65-1eb7-43c1-8fca-3677ee54f737}_prefwidth=15 midlayer1_{7cc4ae65-1eb7-43c1-8fca-3677ee54f737}_minwidth=15 midlayer1_{7cc4ae65-1eb7-43c1-8fca-3677ee54f737}_maxwidth=15 midlayer1_{7cc4ae65-1eb7-43c1-8fca-3677ee54f737}_prefwidth=15 midlayer2_{7cc4ae65-1eb7-43c1-8fca-3677ee54f737}_minwidth=15 midlayer2_{7cc4ae65-1eb7-43c1-8fca-3677ee54f737}_maxwidth=15 midlayer2_{7cc4ae65-1eb7-43c1-8fca-3677ee54f737}_prefwidth=15 midlayer3_{7cc4ae65-1eb7-43c1-8fca-3677ee54f737}_minwidth=15 midlayer3_{7cc4ae65-1eb7-43c1-8fca-3677ee54f737}_maxwidth=15 midlayer3_{7cc4ae65-1eb7-43c1-8fca-3677ee54f737}_prefwidth=15 midlayer4_{7cc4ae65-1eb7-43c1-8fca-3677ee54f737}_minwidth=15 midlayer4_{7cc4ae65-1eb7-43c1-8fca-3677ee54f737}_maxwidth=15 midlayer4_{7cc4ae65-1eb7-43c1-8fca-3677ee54f737}_prefwidth=15 bottomlayer_{7cc4ae65-1eb7-43c1-8fca-3677ee54f737}_minwidth=15 bottomlayer_{7cc4ae65-1eb7-43c1-8fca-3677ee54f737}_maxwidth=15 bottomlayer_{7cc4ae65-1eb7-43c1-8fca-3677ee54f737}_prefwidth=15 substack14={E8C37195-128A-4AA0-B681-9B6788FCEC2F} toplayer_{e8c37195-128a-4aa0-b681-9b6788fcec2f}_minwidth=15 toplayer_{e8c37195-128a-4aa0-b681-9b6788fcec2f}_maxwidth=15 toplayer_{e8c37195-128a-4aa0-b681-9b6788fcec2f}_prefwidth=15 midlayer1_{e8c37195-128a-4aa0-b681-9b6788fcec2f}_minwidth=15 midlayer1_{e8c37195-128a-4aa0-b681-9b6788fcec2f}_maxwidth=15 midlayer1_{e8c37195-128a-4aa0-b681-9b6788fcec2f}_prefwidth=15 midlayer2_{e8c37195-128a-4aa0-b681-9b6788fcec2f}_minwidth=15 midlayer2_{e8c37195-128a-4aa0-b681-9b6788fcec2f}_maxwidth=15 midlayer2_{e8c37195-128a-4aa0-b681-9b6788fcec2f}_prefwidth=15 midlayer3_{e8c37195-128a-4aa0-b681-9b6788fcec2f}_minwidth=15 midlayer3_{e8c37195-128a-4aa0-b681-9b6788fcec2f}_maxwidth=15 midlayer3_{e8c37195-128a-4aa0-b681-9b6788fcec2f}_prefwidth=15 midlayer4_{e8c37195-128a-4aa0-b681-9b6788fcec2f}_minwidth=15 midlayer4_{e8c37195-128a-4aa0-b681-9b6788fcec2f}_maxwidth=15 midlayer4_{e8c37195-128a-4aa0-b681-9b6788fcec2f}_prefwidth=15 bottomlayer_{e8c37195-128a-4aa0-b681-9b6788fcec2f}_minwidth=15 bottomlayer_{e8c37195-128a-4aa0-b681-9b6788fcec2f}_maxwidth=15 bottomlayer_{e8c37195-128a-4aa0-b681-9b6788fcec2f}_prefwidth=15 substack15={92E0C252-34CC-4501-B85F-B111C59C3287} toplayer_{92e0c252-34cc-4501-b85f-b111c59c3287}_minwidth=15 toplayer_{92e0c252-34cc-4501-b85f-b111c59c3287}_maxwidth=15 toplayer_{92e0c252-34cc-4501-b85f-b111c59c3287}_prefwidth=15 midlayer1_{92e0c252-34cc-4501-b85f-b111c59c3287}_minwidth=15 midlayer1_{92e0c252-34cc-4501-b85f-b111c59c3287}_maxwidth=15 midlayer1_{92e0c252-34cc-4501-b85f-b111c59c3287}_prefwidth=15 midlayer2_{92e0c252-34cc-4501-b85f-b111c59c3287}_minwidth=15 midlayer2_{92e0c252-34cc-4501-b85f-b111c59c3287}_maxwidth=15 midlayer2_{92e0c252-34cc-4501-b85f-b111c59c3287}_prefwidth=15 midlayer3_{92e0c252-34cc-4501-b85f-b111c59c3287}_minwidth=15 midlayer3_{92e0c252-34cc-4501-b85f-b111c59c3287}_maxwidth=15 midlayer3_{92e0c252-34cc-4501-b85f-b111c59c3287}_prefwidth=15 midlayer4_{92e0c252-34cc-4501-b85f-b111c59c3287}_minwidth=15 midlayer4_{92e0c252-34cc-4501-b85f-b111c59c3287}_maxwidth=15 midlayer4_{92e0c252-34cc-4501-b85f-b111c59c3287}_prefwidth=15 bottomlayer_{92e0c252-34cc-4501-b85f-b111c59c3287}_minwidth=15 bottomlayer_{92e0c252-34cc-4501-b85f-b111c59c3287}_maxwidth=15 bottomlayer_{92e0c252-34cc-4501-b85f-b111c59c3287}_prefwidth=15 substack16={732F7058-E977-446F-8A06-ECA871B5D75E} toplayer_{732f7058-e977-446f-8a06-eca871b5d75e}_minwidth=15 toplayer_{732f7058-e977-446f-8a06-eca871b5d75e}_maxwidth=15 toplayer_{732f7058-e977-446f-8a06-eca871b5d75e}_prefwidth=15 midlayer1_{732f7058-e977-446f-8a06-eca871b5d75e}_minwidth=15 midlayer1_{732f7058-e977-446f-8a06-eca871b5d75e}_maxwidth=15 midlayer1_{732f7058-e977-446f-8a06-eca871b5d75e}_prefwidth=15 midlayer2_{732f7058-e977-446f-8a06-eca871b5d75e}_minwidth=15 midlayer2_{732f7058-e977-446f-8a06-eca871b5d75e}_maxwidth=15 midlayer2_{732f7058-e977-446f-8a06-eca871b5d75e}_prefwidth=15 midlayer3_{732f7058-e977-446f-8a06-eca871b5d75e}_minwidth=15 midlayer3_{732f7058-e977-446f-8a06-eca871b5d75e}_maxwidth=15 midlayer3_{732f7058-e977-446f-8a06-eca871b5d75e}_prefwidth=15 midlayer4_{732f7058-e977-446f-8a06-eca871b5d75e}_minwidth=15 midlayer4_{732f7058-e977-446f-8a06-eca871b5d75e}_maxwidth=15 midlayer4_{732f7058-e977-446f-8a06-eca871b5d75e}_prefwidth=15 bottomlayer_{732f7058-e977-446f-8a06-eca871b5d75e}_minwidth=15 bottomlayer_{732f7058-e977-446f-8a06-eca871b5d75e}_maxwidth=15 bottomlayer_{732f7058-e977-446f-8a06-eca871b5d75e}_prefwidth=15 substack17={990DA1BC-A1DE-47D8-A675-B5A4E74B5332} toplayer_{990da1bc-a1de-47d8-a675-b5a4e74b5332}_minwidth=15 toplayer_{990da1bc-a1de-47d8-a675-b5a4e74b5332}_maxwidth=15 toplayer_{990da1bc-a1de-47d8-a675-b5a4e74b5332}_prefwidth=15 midlayer1_{990da1bc-a1de-47d8-a675-b5a4e74b5332}_minwidth=15 midlayer1_{990da1bc-a1de-47d8-a675-b5a4e74b5332}_maxwidth=15 midlayer1_{990da1bc-a1de-47d8-a675-b5a4e74b5332}_prefwidth=15 midlayer2_{990da1bc-a1de-47d8-a675-b5a4e74b5332}_minwidth=15 midlayer2_{990da1bc-a1de-47d8-a675-b5a4e74b5332}_maxwidth=15 midlayer2_{990da1bc-a1de-47d8-a675-b5a4e74b5332}_prefwidth=15 midlayer3_{990da1bc-a1de-47d8-a675-b5a4e74b5332}_minwidth=15 midlayer3_{990da1bc-a1de-47d8-a675-b5a4e74b5332}_maxwidth=15 midlayer3_{990da1bc-a1de-47d8-a675-b5a4e74b5332}_prefwidth=15 midlayer4_{990da1bc-a1de-47d8-a675-b5a4e74b5332}_minwidth=15 midlayer4_{990da1bc-a1de-47d8-a675-b5a4e74b5332}_maxwidth=15 midlayer4_{990da1bc-a1de-47d8-a675-b5a4e74b5332}_prefwidth=15 bottomlayer_{990da1bc-a1de-47d8-a675-b5a4e74b5332}_minwidth=15 bottomlayer_{990da1bc-a1de-47d8-a675-b5a4e74b5332}_maxwidth=15 bottomlayer_{990da1bc-a1de-47d8-a675-b5a4e74b5332}_prefwidth=15 maxuncoupledlength=1000
FabricationTestPointUsage TestPointUsage [All] p1: valid=2 allowmultiple=FALSE
FabricationTestpoint Testpoint [All] p1: side=3 testpointundercomponent=TRUE minsize=40 maxsize=100 preferedsize=60 minholesize=0 maxholesize=40 preferedholesize=32 testpointgrid=1 allowsidetop=TRUE allowsidebottom=TRUE usegrid=TRUE gridtolerance=0.01
FanoutControl Fanout_LCC [IsLCC] p1: bgadir=Out bgaviamode=Centered fanoutstyle=Auto fanoutdirection=Alternating viagrid=1 // Fanout_LCC (Default Rule)
FanoutControl Fanout_BGA [IsBGA] p2: bgadir=Out bgaviamode=Centered fanoutstyle=Auto fanoutdirection=Alternating viagrid=1 // Fanout_BGA (Default Rule)
FanoutControl Fanout_Default [All] p4: bgadir=Out bgaviamode=Centered fanoutstyle=Auto fanoutdirection=Alternating viagrid=1 // Fanout_Default (Default Rule)
FanoutControl Fanout_Small [(CompPinCount < 5)] p5: bgadir=Out bgaviamode=Centered fanoutstyle=Auto fanoutdirection=OutThenIn viagrid=1 // Fanout_Small (Default Rule)
Height [All] p1: minheight=0 maxheight=1500 prefheight=500
HoleSize [All] p1: absolutevalues=TRUE maxlimit=500 minlimit=7.87 maxpercent=80.000 minpercent=20.000
HoleToHoleClearance [All] p1: gap=0 allowstackedmicrovias=TRUE
MinimumAnnularRing MinimumAnnularRing_ThermalPadVias [IsVia and InAnyComponent] p1: minimumring=5.91
MinimumAnnularRing [All] p2: minimumring=4.5
MinimumSolderMaskSliver MinimumSolderMaskSliver_Logo [InComponentClass('Logo') vs InComponentClass('Logo')] p1: minsoldermaskwidth=0.1
MinimumSolderMaskSliver [All] p2: minsoldermaskwidth=1
PlaneConnect [All] p1: planeconnectstyle=Relief reliefexpansion=10 reliefentries=4 reliefconductorwidth=10 reliefairgap=10
PolygonConnect PolygonConnect_59 [All vs IsNamedPolygon('PGND') Or  IsNamedPolygon('C102_1') Or  IsNamedPolygon('PGND') Or  IsNamedPolygon('F150_2') Or  IsNamedPolygon('C102_1') Or  IsNamedPolygon('F150_1') Or  IsNamedPolygon('C105_2') Or  IsNamedPolygon('ZCD') Or  IsNamedPolygon('C102_1') Or  IsNamedPolygon('C102_1') Or  IsNamedPolygon('PGND') Or  IsNamedPolygon('PGND') Or  IsNamedPolygon('Line') Or  IsNamedPolygon('F150_1') Or  IsNamedPolygon('ZCD') Or  IsNamedPolygon('Line') Or  IsNamedPolygon('Neutral') Or  IsNamedPolygon('F150_2') Or  IsNamedPolygon('Line') Or  IsNamedPolygon('Neutral') Or  IsNamedPolygon('F150_1') Or  IsNamedPolygon('PGND') Or  IsNamedPolygon('SWNODE') Or  IsNamedPolygon('SWNODE') Or  IsNamedPolygon('SWNODE') Or  IsNamedPolygon('PGND') Or  IsNamedPolygon('Line') Or  IsNamedPolygon('Vbulk1') Or  IsNamedPolygon('C105_2') Or  IsNamedPolygon('PGND') Or  IsNamedPolygon('C105_2') Or  IsNamedPolygon('PGND') Or  IsNamedPolygon('C105_1') Or  IsNamedPolygon('PGND') Or  IsNamedPolygon('Vbulk') Or  IsNamedPolygon('Vbulk') Or  IsNamedPolygon('F150_1') Or  IsNamedPolygon('Vbulk') Or  IsNamedPolygon('PGND') Or  IsNamedPolygon('C105_1') Or  IsNamedPolygon('Neutral') Or  IsNamedPolygon('Neutral') Or  IsNamedPolygon('SWNODE') Or  IsNamedPolygon('C102_1') Or  IsNamedPolygon('F150_2') Or  IsNamedPolygon('C105_1') Or  IsNamedPolygon('Line') Or  IsNamedPolygon('F150_2') Or  IsNamedPolygon('F150_2') Or  IsNamedPolygon('F150_1') Or  IsNamedPolygon('C105_1') Or  IsNamedPolygon('Vbulk1') Or  IsNamedPolygon('PGND') Or  IsNamedPolygon('C105_2') Or  IsNamedPolygon('F150_1') Or  IsNamedPolygon('C105_1') Or  IsNamedPolygon('F150_2') Or  IsNamedPolygon('C102_1') Or  IsNamedPolygon('PGND') Or  IsNamedPolygon('VBB') Or  IsNamedPolygon('12Vp') Or  IsNamedPolygon('J102_1') Or  IsNamedPolygon('J102_1') Or  IsNamedPolygon('Neutral') Or  IsNamedPolygon('Neutral') Or  IsNamedPolygon('PGND') Or  IsNamedPolygon('VBB') Or  IsNamedPolygon('Vbulk') Or  IsNamedPolygon('VBB') Or  IsNamedPolygon('C105_2') Or  IsNamedPolygon('ZCD') Or  IsNamedPolygon('C105_2') Or  IsNamedPolygon('ZCD') Or  IsNamedPolygon('Vbulk') Or  IsNamedPolygon('ZCD') Or  IsNamedPolygon('5Vp') Or  IsNamedPolygon('J102_1') Or  IsNamedPolygon('SWNODE') Or  IsNamedPolygon('PGND') Or  IsNamedPolygon('ZCD') Or  IsNamedPolygon('D106_1') Or  IsNamedPolygon('VBB') Or  IsNamedPolygon('J102_1') Or  IsNamedPolygon('J102_1') Or  IsNamedPolygon('PGND') Or  IsNamedPolygon('VBB') Or  IsNamedPolygon('D106_1') Or  IsNamedPolygon('PGND') Or  IsNamedPolygon('SWNODE') Or  IsNamedPolygon('ZCD') Or  IsNamedPolygon('PGND') Or  IsNamedPolygon('Vbulk1') Or  IsNamedPolygon('ZCD') Or  IsNamedPolygon('Line') Or  IsNamedPolygon('Vbulk') Or  IsNamedPolygon('PGND') Or  IsNamedPolygon('PGND') Or  IsNamedPolygon('VBB') Or  IsNamedPolygon('PGND') Or  IsNamedPolygon('C105_1') Or  IsNamedPolygon('VBB') Or  IsNamedPolygon('ZCD') Or  IsNamedPolygon('Neutral') Or  IsNamedPolygon('ZCD') Or  IsNamedPolygon('PE') Or  IsNamedPolygon('J102_1') Or  IsNamedPolygon('Vbulk') Or  IsNamedPolygon('Vbulk1')] p1: connectstyle=Direct reliefconductorwidth=10 reliefentries=4 polygonreliefangle="90 Angle" airgapwidth=10
PolygonConnect PolygonConnect_58 [All vs IsNamedPolygon('C105_1') Or  IsNamedPolygon('12Vp') Or  IsNamedPolygon('Neutral') Or  IsNamedPolygon('C105_2') Or  IsNamedPolygon('ZCD') Or  IsNamedPolygon('C105_1') Or  IsNamedPolygon('VBB') Or  IsNamedPolygon('PGND') Or  IsNamedPolygon('F150_2') Or  IsNamedPolygon('SWNODE') Or  IsNamedPolygon('PGND') Or  IsNamedPolygon('PGND') Or  IsNamedPolygon('J102_1') Or  IsNamedPolygon('D106_1') Or  IsNamedPolygon('PGND') Or  IsNamedPolygon('C105_2') Or  IsNamedPolygon('SWNODE') Or  IsNamedPolygon('Vbulk') Or  IsNamedPolygon('PGND') Or  IsNamedPolygon('PGND') Or  IsNamedPolygon('PGND') Or  IsNamedPolygon('PGND') Or  IsNamedPolygon('Vbulk') Or  IsNamedPolygon('PGND') Or  IsNamedPolygon('PGND') Or  IsNamedPolygon('D106_1') Or  IsNamedPolygon('Neutral') Or  IsNamedPolygon('PGND') Or  IsNamedPolygon('C105_2') Or  IsNamedPolygon('Vbulk') Or  IsNamedPolygon('SWNODE') Or  IsNamedPolygon('VBB') Or  IsNamedPolygon('J102_1') Or  IsNamedPolygon('VBB') Or  IsNamedPolygon('PGND') Or  IsNamedPolygon('5Vp') Or  IsNamedPolygon('SWNODE') Or  IsNamedPolygon('C105_1') Or  IsNamedPolygon('VBB') Or  IsNamedPolygon('SWNODE') Or  IsNamedPolygon('ZCD') Or  IsNamedPolygon('Vbulk') Or  IsNamedPolygon('Line') Or  IsNamedPolygon('Vbulk1') Or  IsNamedPolygon('PGND') Or  IsNamedPolygon('ZCD') Or  IsNamedPolygon('VBB') Or  IsNamedPolygon('PGND') Or  IsNamedPolygon('ZCD') Or  IsNamedPolygon('Vbulk1') Or  IsNamedPolygon('Neutral') Or  IsNamedPolygon('F150_2') Or  IsNamedPolygon('F150_2') Or  IsNamedPolygon('PGND') Or  IsNamedPolygon('Neutral') Or  IsNamedPolygon('C102_1') Or  IsNamedPolygon('C105_1') Or  IsNamedPolygon('Line') Or  IsNamedPolygon('J102_1') Or  IsNamedPolygon('Neutral') Or  IsNamedPolygon('Neutral') Or  IsNamedPolygon('SWNODE') Or  IsNamedPolygon('ZCD') Or  IsNamedPolygon('J102_1') Or  IsNamedPolygon('J102_1') Or  IsNamedPolygon('PGND') Or  IsNamedPolygon('ZCD') Or  IsNamedPolygon('Vbulk') Or  IsNamedPolygon('Line') Or  IsNamedPolygon('VBB') Or  IsNamedPolygon('Vbulk') Or  IsNamedPolygon('VBB') Or  IsNamedPolygon('Line') Or  IsNamedPolygon('C105_1') Or  IsNamedPolygon('ZCD') Or  IsNamedPolygon('C105_2') Or  IsNamedPolygon('Line') Or  IsNamedPolygon('C105_2') Or  IsNamedPolygon('PGND') Or  IsNamedPolygon('PE') Or  IsNamedPolygon('Neutral') Or  IsNamedPolygon('F150_2') Or  IsNamedPolygon('ZCD') Or  IsNamedPolygon('F150_2') Or  IsNamedPolygon('F150_2') Or  IsNamedPolygon('ZCD') Or  IsNamedPolygon('PGND') Or  IsNamedPolygon('PGND') Or  IsNamedPolygon('Vbulk1') Or  IsNamedPolygon('Line') Or  IsNamedPolygon('ZCD') Or  IsNamedPolygon('C105_1') Or  IsNamedPolygon('J102_1') Or  IsNamedPolygon('Vbulk1') Or  IsNamedPolygon('Vbulk') Or  IsNamedPolygon('C105_2') Or  IsNamedPolygon('PGND')] p2: connectstyle=Direct reliefconductorwidth=10 reliefentries=4 polygonreliefangle="90 Angle" airgapwidth=10
PolygonConnect PolygonConnect_57 [All vs IsNamedPolygon('PGND') Or  IsNamedPolygon('C105_2') Or  IsNamedPolygon('VBB') Or  IsNamedPolygon('5Vp') Or  IsNamedPolygon('ZCD') Or  IsNamedPolygon('J102_1') Or  IsNamedPolygon('PGND') Or  IsNamedPolygon('PGND') Or  IsNamedPolygon('PGND') Or  IsNamedPolygon('PE') Or  IsNamedPolygon('VBB') Or  IsNamedPolygon('VBB') Or  IsNamedPolygon('ZCD') Or  IsNamedPolygon('ZCD') Or  IsNamedPolygon('Line') Or  IsNamedPolygon('PGND') Or  IsNamedPolygon('C102_1') Or  IsNamedPolygon('VBB') Or  IsNamedPolygon('J102_1') Or  IsNamedPolygon('Vbulk') Or  IsNamedPolygon('PGND') Or  IsNamedPolygon('Neutral') Or  IsNamedPolygon('Vbulk') Or  IsNamedPolygon('ZCD') Or  IsNamedPolygon('J102_1') Or  IsNamedPolygon('PGND') Or  IsNamedPolygon('ZCD') Or  IsNamedPolygon('J102_1') Or  IsNamedPolygon('VBB') Or  IsNamedPolygon('Neutral') Or  IsNamedPolygon('PGND') Or  IsNamedPolygon('PGND') Or  IsNamedPolygon('12Vp') Or  IsNamedPolygon('Vbulk') Or  IsNamedPolygon('PGND') Or  IsNamedPolygon('Vbulk') Or  IsNamedPolygon('J102_1') Or  IsNamedPolygon('PGND') Or  IsNamedPolygon('D106_1') Or  IsNamedPolygon('PGND') Or  IsNamedPolygon('Vbulk1') Or  IsNamedPolygon('PGND') Or  IsNamedPolygon('C105_2') Or  IsNamedPolygon('Vbulk') Or  IsNamedPolygon('Neutral') Or  IsNamedPolygon('Vbulk1') Or  IsNamedPolygon('PGND') Or  IsNamedPolygon('PGND') Or  IsNamedPolygon('J102_1') Or  IsNamedPolygon('SWNODE') Or  IsNamedPolygon('Vbulk1') Or  IsNamedPolygon('C105_2') Or  IsNamedPolygon('VBB') Or  IsNamedPolygon('VBB') Or  IsNamedPolygon('ZCD') Or  IsNamedPolygon('SWNODE') Or  IsNamedPolygon('Vbulk') Or  IsNamedPolygon('PGND') Or  IsNamedPolygon('Vbulk') Or  IsNamedPolygon('C105_1') Or  IsNamedPolygon('PGND') Or  IsNamedPolygon('PGND') Or  IsNamedPolygon('ZCD') Or  IsNamedPolygon('C105_2') Or  IsNamedPolygon('D106_1') Or  IsNamedPolygon('PGND') Or  IsNamedPolygon('C105_2') Or  IsNamedPolygon('C105_2') Or  IsNamedPolygon('ZCD') Or  IsNamedPolygon('PGND')] p3: connectstyle=Direct reliefconductorwidth=10 reliefentries=4 polygonreliefangle="90 Angle" airgapwidth=10
PolygonConnect PolygonConnect_56 [All vs IsNamedPolygon('PGND') Or  IsNamedPolygon('C105_2') Or  IsNamedPolygon('VBB') Or  IsNamedPolygon('5Vp') Or  IsNamedPolygon('ZCD') Or  IsNamedPolygon('J102_1') Or  IsNamedPolygon('PGND') Or  IsNamedPolygon('PGND') Or  IsNamedPolygon('PGND') Or  IsNamedPolygon('PE') Or  IsNamedPolygon('VBB') Or  IsNamedPolygon('VBB') Or  IsNamedPolygon('ZCD') Or  IsNamedPolygon('ZCD') Or  IsNamedPolygon('Line') Or  IsNamedPolygon('PGND') Or  IsNamedPolygon('C102_1') Or  IsNamedPolygon('VBB') Or  IsNamedPolygon('J102_1') Or  IsNamedPolygon('Vbulk') Or  IsNamedPolygon('PGND') Or  IsNamedPolygon('Neutral') Or  IsNamedPolygon('Vbulk') Or  IsNamedPolygon('ZCD') Or  IsNamedPolygon('J102_1') Or  IsNamedPolygon('PGND') Or  IsNamedPolygon('ZCD') Or  IsNamedPolygon('J102_1') Or  IsNamedPolygon('VBB') Or  IsNamedPolygon('Neutral') Or  IsNamedPolygon('PGND') Or  IsNamedPolygon('PGND') Or  IsNamedPolygon('12Vp') Or  IsNamedPolygon('Vbulk') Or  IsNamedPolygon('PGND') Or  IsNamedPolygon('Vbulk') Or  IsNamedPolygon('J102_1') Or  IsNamedPolygon('PGND') Or  IsNamedPolygon('D106_1') Or  IsNamedPolygon('PGND') Or  IsNamedPolygon('Vbulk1') Or  IsNamedPolygon('PGND') Or  IsNamedPolygon('C105_2') Or  IsNamedPolygon('Vbulk') Or  IsNamedPolygon('Neutral') Or  IsNamedPolygon('Vbulk1') Or  IsNamedPolygon('PGND') Or  IsNamedPolygon('PGND') Or  IsNamedPolygon('J102_1') Or  IsNamedPolygon('SWNODE') Or  IsNamedPolygon('Vbulk1') Or  IsNamedPolygon('C105_2') Or  IsNamedPolygon('VBB') Or  IsNamedPolygon('VBB') Or  IsNamedPolygon('ZCD') Or  IsNamedPolygon('SWNODE') Or  IsNamedPolygon('Vbulk') Or  IsNamedPolygon('PGND') Or  IsNamedPolygon('Vbulk') Or  IsNamedPolygon('C105_1') Or  IsNamedPolygon('PGND') Or  IsNamedPolygon('PGND') Or  IsNamedPolygon('ZCD') Or  IsNamedPolygon('C105_2') Or  IsNamedPolygon('D106_1') Or  IsNamedPolygon('PGND') Or  IsNamedPolygon('C105_2') Or  IsNamedPolygon('C105_2') Or  IsNamedPolygon('ZCD') Or  IsNamedPolygon('PGND')] p4: thpad.connectstyle=Direct thpad.reliefconductorwidth=10 thpad.reliefentries=4 thpad.polygonreliefangle="90 Angle" thpad.airgapwidth=10 smdpad.connectstyle=Relief smdpad.reliefconductorwidth=10 smdpad.reliefentries=4 smdpad.polygonreliefangle="90 Angle" smdpad.airgapwidth=10 via.connectstyle=Relief via.reliefconductorwidth=10 via.reliefentries=4 via.polygonreliefangle="90 Angle" via.airgapwidth=10
PolygonConnect PolygonConnect_55 [All vs IsNamedPolygon('SWNODE') Or  IsNamedPolygon('ZCD') Or  IsNamedPolygon('PGND') Or  IsNamedPolygon('PGND') Or  IsNamedPolygon('PGND') Or  IsNamedPolygon('PGND') Or  IsNamedPolygon('PGND') Or  IsNamedPolygon('PGND') Or  IsNamedPolygon('Vbulk') Or  IsNamedPolygon('D106_1') Or  IsNamedPolygon('Vbulk') Or  IsNamedPolygon('D106_1') Or  IsNamedPolygon('VBB') Or  IsNamedPolygon('PGND') Or  IsNamedPolygon('PGND') Or  IsNamedPolygon('Vbulk') Or  IsNamedPolygon('VBB') Or  IsNamedPolygon('ZCD') Or  IsNamedPolygon('Vbulk') Or  IsNamedPolygon('ZCD') Or  IsNamedPolygon('VBB') Or  IsNamedPolygon('VBB') Or  IsNamedPolygon('VBB') Or  IsNamedPolygon('VBB') Or  IsNamedPolygon('VBB') Or  IsNamedPolygon('ZCD') Or  IsNamedPolygon('C102_1') Or  IsNamedPolygon('12Vp') Or  IsNamedPolygon('C105_1') Or  IsNamedPolygon('PGND') Or  IsNamedPolygon('SWNODE') Or  IsNamedPolygon('Vbulk') Or  IsNamedPolygon('Vbulk1') Or  IsNamedPolygon('Vbulk1') Or  IsNamedPolygon('Neutral') Or  IsNamedPolygon('ZCD') Or  IsNamedPolygon('Neutral') Or  IsNamedPolygon('ZCD') Or  IsNamedPolygon('5Vp') Or  IsNamedPolygon('Neutral') Or  IsNamedPolygon('ZCD') Or  IsNamedPolygon('Line') Or  IsNamedPolygon('ZCD')] p5: connectstyle=Direct reliefconductorwidth=10 reliefentries=4 polygonreliefangle="90 Angle" airgapwidth=10
PolygonConnect PolygonConnect_54 [All vs IsNamedPolygon('12Vp') Or  IsNamedPolygon('SWNODE') Or  IsNamedPolygon('D403_2') Or  IsNamedPolygon('D403_2') Or  IsNamedPolygon('PGND') Or  IsNamedPolygon('BOTTOM_LAYER_NETC106_2_P030') Or  IsNamedPolygon('C102_1') Or  IsNamedPolygon('SGND') Or  IsNamedPolygon('TOP_LAYER_54V1_P046') Or  IsNamedPolygon('TOP_LAYER_54V2_P048') Or  IsNamedPolygon('TOP_LAYER_54V2_P048') Or  IsNamedPolygon('C108_1') Or  IsNamedPolygon('C108_1') Or  IsNamedPolygon('C108_1') Or  IsNamedPolygon('C108_1') Or  IsNamedPolygon('C108_1') Or  IsNamedPolygon('C108_1') Or  IsNamedPolygon('PGND') Or  IsNamedPolygon('ZCD') Or  IsNamedPolygon('Line') Or  IsNamedPolygon('5Vp') Or  IsNamedPolygon('12Vp') Or  IsNamedPolygon('T200_4') Or  IsNamedPolygon('T200_6') Or  IsNamedPolygon('SWNODE3') Or  IsNamedPolygon('T200_4') Or  IsNamedPolygon('T200_6') Or  IsNamedPolygon('SWNODE4') Or  IsNamedPolygon('VSR') Or  IsNamedPolygon('TOP_LAYER_IOUT_SNS_P092') Or  IsNamedPolygon('SIGNAL_LAYER_2_VBB_P094') Or  IsNamedPolygon('Vbulk1') Or  IsNamedPolygon('TOP_LAYER_VBULK_P104') Or  IsNamedPolygon('SIGNAL_LAYER_1_VBULK1_P106') Or  IsNamedPolygon('Line') Or  IsNamedPolygon('Line') Or  IsNamedPolygon('D404_2') Or  IsNamedPolygon('Vbulk') Or  IsNamedPolygon('D400_2') Or  IsNamedPolygon('SGND') Or  IsNamedPolygon('PGND') Or  IsNamedPolygon('TOP_LAYER_12VS_P126') Or  IsNamedPolygon('LEG3_HS_DRV') Or  IsNamedPolygon('LEG4_LS_DRV') Or  IsNamedPolygon('LEG4_HS_DRV') Or  IsNamedPolygon('SWNODE4') Or  IsNamedPolygon('SWNODE3') Or  IsNamedPolygon('T200_6') Or  IsNamedPolygon('T200_4') Or  IsNamedPolygon('VBB') Or  IsNamedPolygon('5Vs') Or  IsNamedPolygon('SGND') Or  IsNamedPolygon('Iout_SNS') Or  IsNamedPolygon('SGND') Or  IsNamedPolygon('SWNODE3') Or  IsNamedPolygon('SWNODE3') Or  IsNamedPolygon('SWNODE3') Or  IsNamedPolygon('SWNODE3') Or  IsNamedPolygon('SGND') Or  IsNamedPolygon('SGND') Or  IsNamedPolygon('SGND') Or  IsNamedPolygon('SWNODE4') Or  IsNamedPolygon('SWNODE4') Or  IsNamedPolygon('SWNODE4') Or  IsNamedPolygon('VSR') Or  IsNamedPolygon('SWNODE3') Or  IsNamedPolygon('SGND') Or  IsNamedPolygon('SGND') Or  IsNamedPolygon('SGND') Or  IsNamedPolygon('SGND') Or  IsNamedPolygon('SGND') Or  IsNamedPolygon('SGND') Or  IsNamedPolygon('54V1') Or  IsNamedPolygon('SGND') Or  IsNamedPolygon('VSR') Or  IsNamedPolygon('C102_1') Or  IsNamedPolygon('C102_1') Or  IsNamedPolygon('C102_1') Or  IsNamedPolygon('C102_1') Or  IsNamedPolygon('C102_1') Or  IsNamedPolygon('ZCD') Or  IsNamedPolygon('PGND') Or  IsNamedPolygon('PGND') Or  IsNamedPolygon('Vbulk1') Or  IsNamedPolygon('Vbulk') Or  IsNamedPolygon('Vbulk1') Or  IsNamedPolygon('Vbulk1') Or  IsNamedPolygon('ZCD') Or  IsNamedPolygon('Neutral') Or  IsNamedPolygon('Neutral') Or  IsNamedPolygon('C106_2') Or  IsNamedPolygon('C106_2') Or  IsNamedPolygon('C106_2') Or  IsNamedPolygon('SWNODE') Or  IsNamedPolygon('Vbulk1') Or  IsNamedPolygon('Earth1') Or  IsNamedPolygon('Earth1') Or  IsNamedPolygon('Earth1') Or  IsNamedPolygon('Earth1') Or  IsNamedPolygon('Earth1') Or  IsNamedPolygon('Earth1') Or  IsNamedPolygon('ZCD') Or  IsNamedPolygon('VBB') Or  IsNamedPolygon('PGND') Or  IsNamedPolygon('D106_1') Or  IsNamedPolygon('PGND') Or  IsNamedPolygon('PGND') Or  IsNamedPolygon('D106_1') Or  IsNamedPolygon('Vbulk') Or  IsNamedPolygon('D106_1') Or  IsNamedPolygon('PGND') Or  IsNamedPolygon('VBB') Or  IsNamedPolygon('VBB') Or  IsNamedPolygon('PGND') Or  IsNamedPolygon('PGND') Or  IsNamedPolygon('PGND') Or  IsNamedPolygon('PGND') Or  IsNamedPolygon('PGND') Or  IsNamedPolygon('ZCD') Or  IsNamedPolygon('ZCD') Or  IsNamedPolygon('C412_2') Or  IsNamedPolygon('VBB') Or  IsNamedPolygon('PGND') Or  IsNamedPolygon('PGND') Or  IsNamedPolygon('PGND') Or  IsNamedPolygon('PGND') Or  IsNamedPolygon('PGND') Or  IsNamedPolygon('PGND') Or  IsNamedPolygon('PGND') Or  IsNamedPolygon('Vbulk') Or  IsNamedPolygon('D404_2') Or  IsNamedPolygon('PGND') Or  IsNamedPolygon('Iout_SNS') Or  IsNamedPolygon('54V2') Or  IsNamedPolygon('54V2') Or  IsNamedPolygon('54V2') Or  IsNamedPolygon('54V2') Or  IsNamedPolygon('VSR') Or  IsNamedPolygon('VSR') Or  IsNamedPolygon('Iout_SNS') Or  IsNamedPolygon('SGND') Or  IsNamedPolygon('SGND') Or  IsNamedPolygon('BOTTOM_LAYER_54V1_P154') Or  IsNamedPolygon('ZCD') Or  IsNamedPolygon('PGND')] p6: connectstyle=Direct reliefconductorwidth=10 reliefentries=4 polygonreliefangle="90 Angle" airgapwidth=10
PolygonConnect PolygonConnect_53 [All vs IsNamedPolygon('BOTTOM_LAYER_54V1_P350')] p7: connectstyle=Direct reliefconductorwidth=10 reliefentries=4 polygonreliefangle="90 Angle" airgapwidth=10
PolygonConnect PolygonConnect_52 [All vs IsNamedPolygon('TOP_LAYER_54V1_P046')] p8: connectstyle=Direct reliefconductorwidth=10 reliefentries=4 polygonreliefangle="90 Angle" airgapwidth=10
PolygonConnect PolygonConnect_51 [All vs IsNamedPolygon('SIGNAL_LAYER_1_VBULK1_P106')] p9: connectstyle=Direct reliefconductorwidth=10 reliefentries=4 polygonreliefangle="90 Angle" airgapwidth=10
PolygonConnect PolygonConnect_50 [All vs IsNamedPolygon('BOTTOM_LAYER_54V1_P128')] p10: connectstyle=Direct reliefconductorwidth=10 reliefentries=4 polygonreliefangle="90 Angle" airgapwidth=10
PolygonConnect PolygonConnect_49 [All vs IsNamedPolygon('BOTTOM_LAYER_54V1_P128')] p11: connectstyle=Direct reliefconductorwidth=10 reliefentries=4 polygonreliefangle="90 Angle" airgapwidth=10
PolygonConnect PolygonConnect_48 [All vs IsNamedPolygon('BOTTOM_LAYER_54V1_P128')] p12: connectstyle=Direct reliefconductorwidth=10 reliefentries=4 polygonreliefangle="90 Angle" airgapwidth=10
PolygonConnect PolygonConnect_47 [All vs IsNamedPolygon('BOTTOM_LAYER_54V1_P128')] p13: connectstyle=Direct reliefconductorwidth=10 reliefentries=4 polygonreliefangle="90 Angle" airgapwidth=10
PolygonConnect PolygonConnect_46 [All vs IsNamedPolygon('PGND') Or  IsNamedPolygon('T200_4') Or  IsNamedPolygon('VBB') Or  IsNamedPolygon('SWNODE3') Or  IsNamedPolygon('LEG4_LS_DRV') Or  IsNamedPolygon('Iout_SNS') Or  IsNamedPolygon('SWNODE3') Or  IsNamedPolygon('T200_6') Or  IsNamedPolygon('SGND') Or  IsNamedPolygon('SIGNAL_LAYER_1_VBULK1_P106') Or  IsNamedPolygon('LEG3_HS_DRV') Or  IsNamedPolygon('TOP_LAYER_12VS_P126') Or  IsNamedPolygon('LEG4_HS_DRV') Or  IsNamedPolygon('SWNODE3') Or  IsNamedPolygon('SGND') Or  IsNamedPolygon('BOTTOM_LAYER_54V1_P128') Or  IsNamedPolygon('SGND') Or  IsNamedPolygon('Line') Or  IsNamedPolygon('TOP_LAYER_IOUT_SNS_P092') Or  IsNamedPolygon('C108_1') Or  IsNamedPolygon('D403_2') Or  IsNamedPolygon('SWNODE') Or  IsNamedPolygon('SIGNAL_LAYER_2_VBB_P094') Or  IsNamedPolygon('Vbulk') Or  IsNamedPolygon('D404_2') Or  IsNamedPolygon('VSR') Or  IsNamedPolygon('C108_1') Or  IsNamedPolygon('C108_1') Or  IsNamedPolygon('5Vp') Or  IsNamedPolygon('C108_1') Or  IsNamedPolygon('PGND') Or  IsNamedPolygon('D400_2') Or  IsNamedPolygon('SWNODE3') Or  IsNamedPolygon('Line') Or  IsNamedPolygon('C108_1') Or  IsNamedPolygon('TOP_LAYER_VBULK_P104') Or  IsNamedPolygon('Vbulk1') Or  IsNamedPolygon('T200_6') Or  IsNamedPolygon('T200_6') Or  IsNamedPolygon('SWNODE4') Or  IsNamedPolygon('C108_1') Or  IsNamedPolygon('D403_2') Or  IsNamedPolygon('PGND') Or  IsNamedPolygon('T200_4') Or  IsNamedPolygon('Line') Or  IsNamedPolygon('5Vs') Or  IsNamedPolygon('12Vp') Or  IsNamedPolygon('C102_1') Or  IsNamedPolygon('SGND') Or  IsNamedPolygon('TOP_LAYER_54V2_P048') Or  IsNamedPolygon('TOP_LAYER_54V1_P046') Or  IsNamedPolygon('SWNODE4') Or  IsNamedPolygon('ZCD') Or  IsNamedPolygon('SWNODE3') Or  IsNamedPolygon('SWNODE3') Or  IsNamedPolygon('BOTTOM_LAYER_NETC106_2_P030') Or  IsNamedPolygon('TOP_LAYER_54V2_P048') Or  IsNamedPolygon('T200_4') Or  IsNamedPolygon('SWNODE4') Or  IsNamedPolygon('SWNODE4') Or  IsNamedPolygon('SGND') Or  IsNamedPolygon('SGND') Or  IsNamedPolygon('SGND') Or  IsNamedPolygon('SWNODE4') Or  IsNamedPolygon('VSR') Or  IsNamedPolygon('SWNODE3') Or  IsNamedPolygon('SGND') Or  IsNamedPolygon('SGND') Or  IsNamedPolygon('SGND') Or  IsNamedPolygon('SGND') Or  IsNamedPolygon('SGND') Or  IsNamedPolygon('SGND') Or  IsNamedPolygon('BOTTOM_LAYER_54V1_P128') Or  IsNamedPolygon('SGND') Or  IsNamedPolygon('VSR') Or  IsNamedPolygon('C102_1') Or  IsNamedPolygon('C102_1') Or  IsNamedPolygon('C102_1') Or  IsNamedPolygon('C102_1') Or  IsNamedPolygon('C102_1') Or  IsNamedPolygon('ZCD') Or  IsNamedPolygon('PGND') Or  IsNamedPolygon('PGND') Or  IsNamedPolygon('Vbulk1') Or  IsNamedPolygon('Vbulk') Or  IsNamedPolygon('Vbulk1') Or  IsNamedPolygon('Vbulk1') Or  IsNamedPolygon('ZCD') Or  IsNamedPolygon('Neutral') Or  IsNamedPolygon('Neutral') Or  IsNamedPolygon('C106_2') Or  IsNamedPolygon('C106_2') Or  IsNamedPolygon('C106_2') Or  IsNamedPolygon('SWNODE') Or  IsNamedPolygon('Vbulk1') Or  IsNamedPolygon('Earth1') Or  IsNamedPolygon('Earth1') Or  IsNamedPolygon('Earth1') Or  IsNamedPolygon('Earth1') Or  IsNamedPolygon('Earth1') Or  IsNamedPolygon('Earth1') Or  IsNamedPolygon('ZCD') Or  IsNamedPolygon('VBB') Or  IsNamedPolygon('PGND') Or  IsNamedPolygon('D106_1') Or  IsNamedPolygon('PGND') Or  IsNamedPolygon('PGND') Or  IsNamedPolygon('D106_1') Or  IsNamedPolygon('Vbulk') Or  IsNamedPolygon('D106_1') Or  IsNamedPolygon('PGND') Or  IsNamedPolygon('VBB') Or  IsNamedPolygon('VBB') Or  IsNamedPolygon('PGND') Or  IsNamedPolygon('PGND') Or  IsNamedPolygon('PGND') Or  IsNamedPolygon('PGND') Or  IsNamedPolygon('PGND') Or  IsNamedPolygon('ZCD') Or  IsNamedPolygon('ZCD') Or  IsNamedPolygon('C412_2') Or  IsNamedPolygon('VBB') Or  IsNamedPolygon('PGND') Or  IsNamedPolygon('PGND') Or  IsNamedPolygon('PGND') Or  IsNamedPolygon('PGND') Or  IsNamedPolygon('PGND') Or  IsNamedPolygon('PGND') Or  IsNamedPolygon('PGND') Or  IsNamedPolygon('Vbulk') Or  IsNamedPolygon('D404_2') Or  IsNamedPolygon('PGND') Or  IsNamedPolygon('Iout_SNS') Or  IsNamedPolygon('54V2')] p14: connectstyle=Direct reliefconductorwidth=10 reliefentries=4 polygonreliefangle="90 Angle" airgapwidth=10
